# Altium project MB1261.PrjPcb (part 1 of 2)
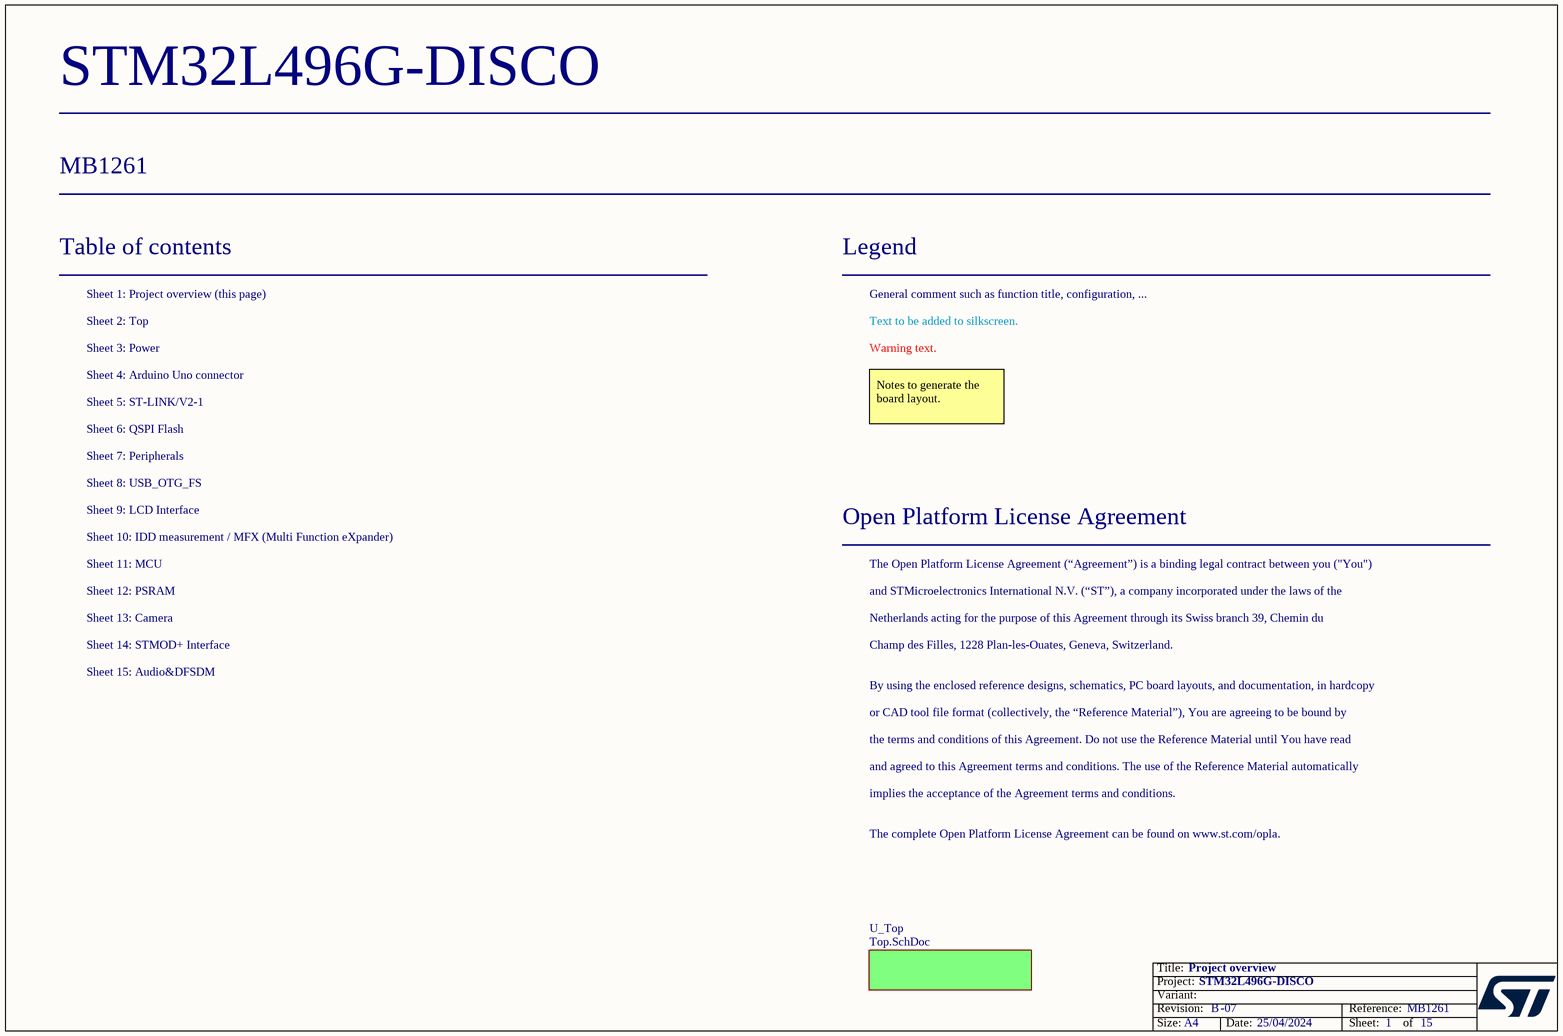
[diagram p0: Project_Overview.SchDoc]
Board_Reference: MB1261; Board_PCB_Revision: B; Board_name: STM32L496G-DISCO; Board_Document_Date: 25/04/2024; Board_Assembly_revision: 07
15 sheets, 337 parts. Net scope: flat (ports and power ports of the same name join across sheets).
Board file: MB1261.PcbDoc
Sheets:
  Project_Overview.SchDoc
    U_Top = Top.SchDoc
      Arduino_ Connectors = Arduino_ Connectors.SchDoc
      Camera Interface = Camera.SchDoc
      IDD = IDD_measurement.SchDoc
      TFT_LCD = LCD.SchDoc
      MCU = MCU.SchDoc
      Peripherals = Peripherals.SchDoc
      Power = Power.SchDoc
      PSRAM = PSRAM.SchDoc
      QSPI = QSPI.SchDoc
      ST_LINK = ST_LINK_V2-1_2.SCHDOC
      OTG = USB_OTG_FS.SchDoc
      STMOD+ = STMOD+.SchDoc
      Audio = Audio.SchDoc

## Sheet Project_Overview.SchDoc: Project overview
size A4; Date: Not used; ApprovedBy: Not used; CheckedBy: Not used; Author: Not used; CompanyName: STMicroelectronics; DrawnBy: Not used; Engineer: Not used; Organization: Not used; Address1: Not used; Address2: Not used; Address3: Not used; Address4: Not used; DocumentNumber: Not used; Revision: Not used; SheetNumber: 1; SheetTotal: 15

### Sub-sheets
U_Top = Top.SchDoc: no entries

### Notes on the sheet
- Table of contents
- Sheet 1: Project overview (this page)
- Legend
- General comment such as function title, configuration, ...
- Sheet 2: Top
- Sheet 3: Power
- Sheet 4: Arduino Uno connector
- Text to be added to silkscreen.
- Warning text.
- Sheet 6: QSPI Flash
- Sheet 5: ST-LINK/V2-1
- Notes to generate the board layout.
- Sheet 7: Peripherals
- Sheet 9: LCD Interface
- Sheet 8: USB_OTG_FS
- Sheet 10: IDD measurement / MFX (Multi Function eXpander)
- Sheet 11: MCU
- Open Platform License Agreement
- The Open Platform License Agreement (“Agreement”) is a binding legal contract between you ("You")
- Sheet 12: PSRAM
- Sheet 13: Camera
- Sheet 14: STMOD+ Interface
- and STMicroelectronics International N.V. (“ST”), a company incorporated under the laws of the
- Netherlands acting for the purpose of this Agreement through its Swiss branch 39, Chemin du
- Champ des Filles, 1228 Plan-les-Ouates, Geneva, Switzerland.
- Sheet 15: Audio&DFSDM
- By using the enclosed reference designs, schematics, PC board layouts, and documentation, in hardcopy
- or CAD tool file format (collectively, the “Reference Material”), You are agreeing to be bound by
- the terms and conditions of this Agreement. Do not use the Reference Material until You have read
- and agreed to this Agreement terms and conditions. The use of the Reference Material automatically
- implies the acceptance of the Agreement terms and conditions.
- The complete Open Platform License Agreement can be found on www.st.com/opla.

## Sheet Top.SchDoc: TOP
size A3; Author: P.A.; CompanyName: STMicroelectronics; Organization: Microcontrollers Division; Address1: 12, Rue Jules HOROWITZ; Address2: 38019 Grenoble; Address3: FRANCE; DocumentNumber: MB1261; Revision: B.01; SheetNumber: 2; SheetTotal: 15; Project: STM32L496G-DISCO
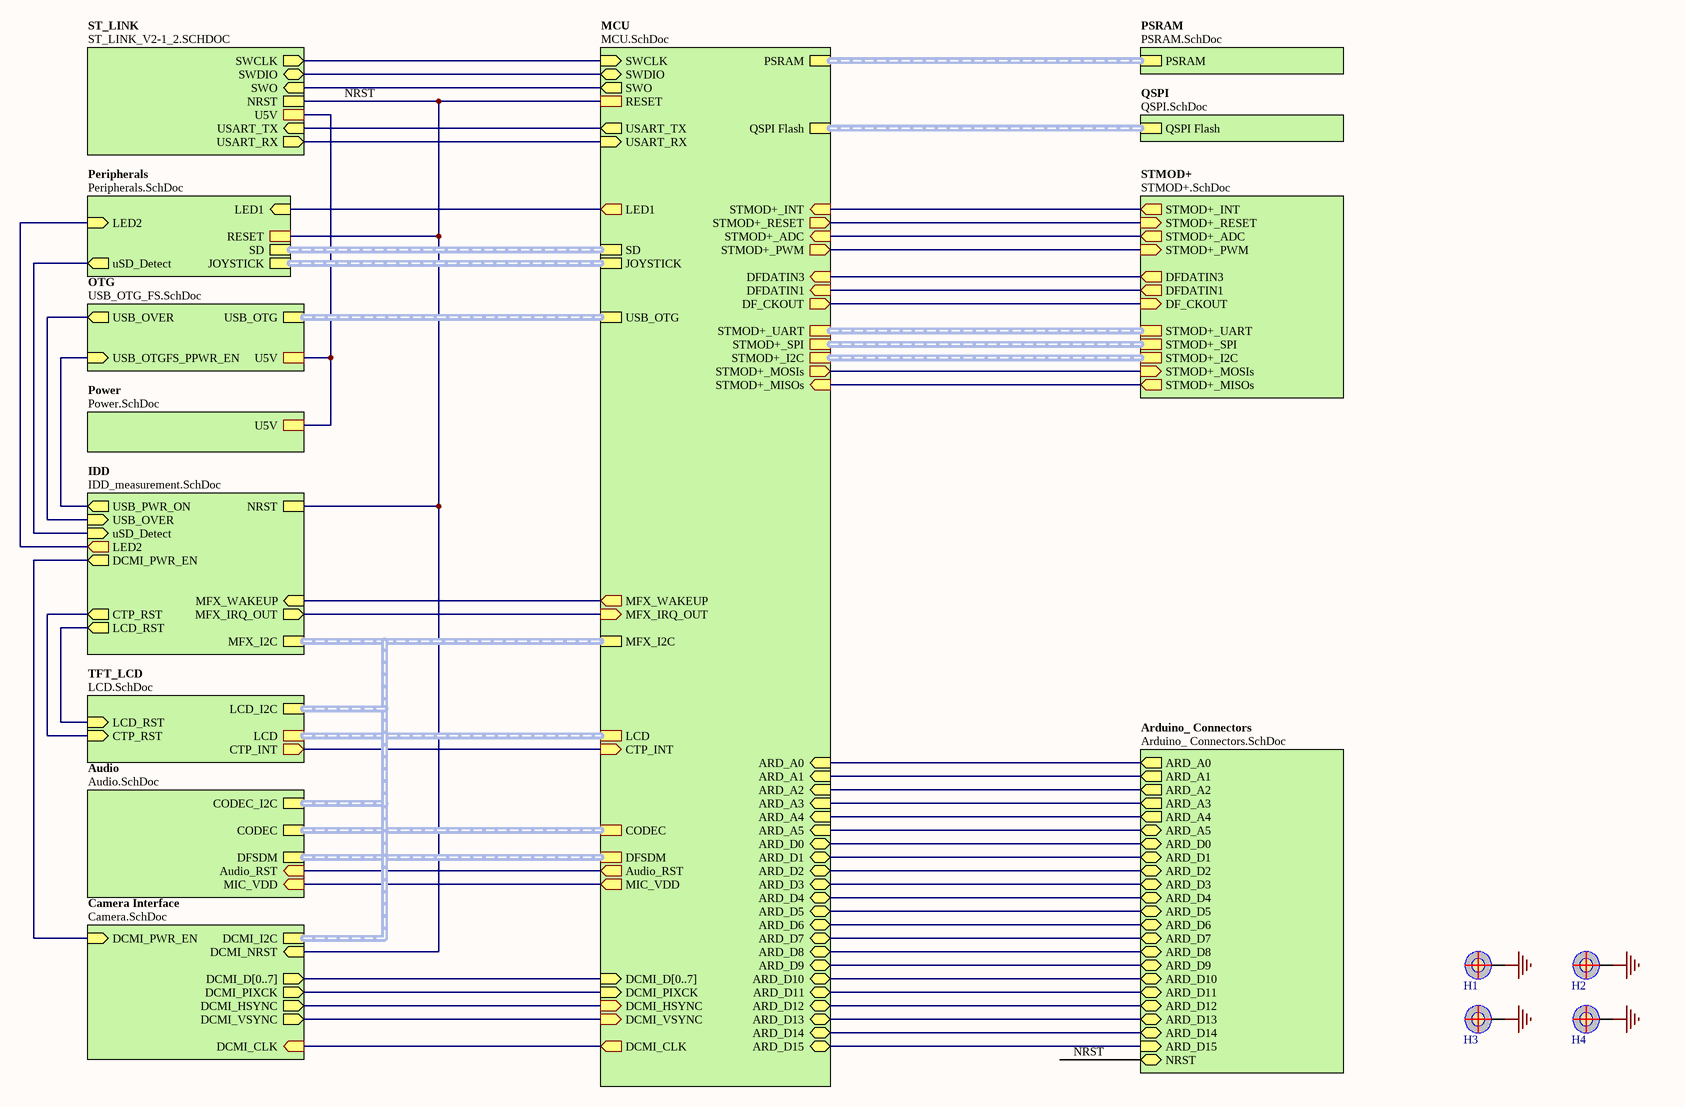
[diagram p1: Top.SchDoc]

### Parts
H1  POSITION HOLE  [Hole_C7d3r5]  (value not drawn)  (no BOM)
H2  POSITION HOLE  [Hole_C7d3r5]  (value not drawn)  (no BOM)
H3  POSITION HOLE  [Hole_C7d3r5]  (value not drawn)  (no BOM)
H4  POSITION HOLE  [Hole_C7d3r5]  (value not drawn)  (no BOM)

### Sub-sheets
Arduino_ Connectors = Arduino_ Connectors.SchDoc: NRST (bidir), ARD_A0 (out), ARD_A1 (out), ARD_A2 (out), ARD_A3 (out), ARD_A4 (out), ARD_A5 (bidir), ARD_D5 (bidir), ARD_D4 (bidir), ARD_D3 (bidir), ARD_D2 (bidir), ARD_D1 (bidir), ARD_D0 (bidir), ARD_D13 (bidir), ARD_D12 (bidir), ARD_D11 (bidir), ARD_D10 (bidir), ARD_D9 (bidir), ARD_D8 (bidir), ARD_D6 (bidir), ARD_D7 (bidir), ARD_D15 (in), ARD_D14 (bidir)
Audio = Audio.SchDoc: CODEC (harness SAI), CODEC_I2C (harness I2C), DFSDM (harness DFSDM), MIC_VDD (in), Audio_RST (in)
Camera Interface = Camera.SchDoc: DCMI_D[0..7] (out), DCMI_NRST (in), DCMI_PWR_EN (in), DCMI_VSYNC (out), DCMI_HSYNC (out), DCMI_PIXCK (out), DCMI_I2C (harness I2C), DCMI_CLK (in)
IDD = IDD_measurement.SchDoc: MFX_IRQ_OUT (out), MFX_WAKEUP (in), NRST, MFX_I2C (harness I2C), USB_PWR_ON (out), DCMI_PWR_EN (out), uSD_Detect (in), USB_OVER (in), CTP_RST (out), LCD_RST (out), LED2 (out)
MCU = MCU.SchDoc: QSPI Flash (harness QSPI), PSRAM (harness PSRAM), SD (harness SD), JOYSTICK (harness JOYSTICK), USB_OTG (harness USB_OTG), MFX_IRQ_OUT (in), MFX_WAKEUP (out), ARD_A0 (in), MFX_I2C (harness I2C), ARD_A1 (in), ARD_A2 (in), ARD_A3 (in), ARD_A4 (in), ARD_A5 (in), ARD_D0 (bidir), ARD_D1 (bidir), ARD_D2 (bidir), ARD_D3 (bidir), ARD_D4 (bidir), ARD_D5 (bidir), ARD_D6 (bidir), ARD_D7 (bidir), ARD_D8 (bidir), ARD_D9 (bidir), ARD_D10 (bidir), ARD_D11 (bidir), ARD_D12 (bidir), ARD_D13 (bidir), ARD_D14 (bidir), ARD_D15 (bidir), USART_TX (out), USART_RX (in), SWCLK (in), SWDIO (bidir), SWO (out), DCMI_D[0..7] (in), DCMI_VSYNC (in), DCMI_HSYNC (in), DCMI_PIXCK (in), STMOD+_UART (harness UART), STMOD+_I2C (harness I2C), STMOD+_INT (in), STMOD+_RESET (out), STMOD+_ADC (in), STMOD+_PWM (out), STMOD+_MOSIs (out), STMOD+_MISOs (in), STMOD+_SPI (harness SPI), DFDATIN3 (in), DFDATIN1 (in), DFSDM (harness DFSDM), MIC_VDD (out), CODEC (harness SAI), LED1 (out), RESET, DCMI_CLK (out), LCD (harness LCD), CTP_INT (in), DF_CKOUT (out), Audio_RST (out)
OTG = USB_OTG_FS.SchDoc: USB_OTG (harness USB_OTG), USB_OTGFS_PPWR_EN (in), USB_OVER (out), U5V
Peripherals = Peripherals.SchDoc: LED1 (in), SD (harness SD), JOYSTICK (harness JOYSTICK), LED2 (in), uSD_Detect (out), RESET
Power = Power.SchDoc: U5V
PSRAM = PSRAM.SchDoc: PSRAM (harness PSRAM)
QSPI = QSPI.SchDoc: QSPI Flash (harness QSPI)
ST_LINK = ST_LINK_V2-1_2.SCHDOC: NRST, SWCLK (out), SWDIO (bidir), SWO (in), USART_TX (in), USART_RX (out), U5V
STMOD+ = STMOD+.SchDoc: STMOD+_INT (out), STMOD+_RESET (in), STMOD+_ADC (out), DFDATIN3 (out), STMOD+_PWM (in), DFDATIN1 (out), STMOD+_UART (harness UART), STMOD+_SPI (harness SPI), STMOD+_I2C (harness I2C), STMOD+_MOSIs (in), STMOD+_MISOs (out), DF_CKOUT (in)
TFT_LCD = LCD.SchDoc: LCD_I2C (harness I2C), CTP_RST (in), LCD_RST (in), LCD (harness LCD), CTP_INT (out)

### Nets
GND: H1.1 H2.1 H3.1 H4.1
NRST: sheet Arduino_ Connectors/NRST, sheet Camera Interface/DCMI_NRST, sheet IDD/NRST, sheet MCU/RESET, sheet Peripherals/RESET, sheet ST_LINK/NRST
(unnamed): sheet Arduino_ Connectors/ARD_A0, sheet MCU/ARD_A0
(unnamed): sheet Arduino_ Connectors/ARD_A1, sheet MCU/ARD_A1  [a separate net that carries the same name]
(unnamed): sheet Arduino_ Connectors/ARD_A2, sheet MCU/ARD_A2  [a separate net that carries the same name]
(unnamed): sheet Arduino_ Connectors/ARD_A3, sheet MCU/ARD_A3  [a separate net that carries the same name]
(unnamed): sheet Arduino_ Connectors/ARD_A4, sheet MCU/ARD_A4  [a separate net that carries the same name]
(unnamed): sheet Arduino_ Connectors/ARD_A5, sheet MCU/ARD_A5  [a separate net that carries the same name]
(unnamed): sheet Arduino_ Connectors/ARD_D5, sheet MCU/ARD_D5  [a separate net that carries the same name]
(unnamed): sheet Arduino_ Connectors/ARD_D4, sheet MCU/ARD_D4  [a separate net that carries the same name]
(unnamed): sheet Arduino_ Connectors/ARD_D3, sheet MCU/ARD_D3  [a separate net that carries the same name]
(unnamed): sheet Arduino_ Connectors/ARD_D2, sheet MCU/ARD_D2  [a separate net that carries the same name]
(unnamed): sheet Arduino_ Connectors/ARD_D1, sheet MCU/ARD_D1  [a separate net that carries the same name]
(unnamed): sheet Arduino_ Connectors/ARD_D0, sheet MCU/ARD_D0  [a separate net that carries the same name]
(unnamed): sheet Arduino_ Connectors/ARD_D13, sheet MCU/ARD_D13  [a separate net that carries the same name]
(unnamed): sheet Arduino_ Connectors/ARD_D12, sheet MCU/ARD_D12  [a separate net that carries the same name]
(unnamed): sheet Arduino_ Connectors/ARD_D11, sheet MCU/ARD_D11  [a separate net that carries the same name]
(unnamed): sheet Arduino_ Connectors/ARD_D10, sheet MCU/ARD_D10  [a separate net that carries the same name]
(unnamed): sheet Arduino_ Connectors/ARD_D9, sheet MCU/ARD_D9  [a separate net that carries the same name]
(unnamed): sheet Arduino_ Connectors/ARD_D8, sheet MCU/ARD_D8  [a separate net that carries the same name]
(unnamed): sheet Arduino_ Connectors/ARD_D6, sheet MCU/ARD_D6  [a separate net that carries the same name]
(unnamed): sheet Arduino_ Connectors/ARD_D7, sheet MCU/ARD_D7  [a separate net that carries the same name]
(unnamed): sheet Arduino_ Connectors/ARD_D15, sheet MCU/ARD_D15  [a separate net that carries the same name]
(unnamed): sheet Arduino_ Connectors/ARD_D14, sheet MCU/ARD_D14  [a separate net that carries the same name]
(unnamed): sheet Camera Interface/DCMI_PWR_EN, sheet IDD/DCMI_PWR_EN  [a separate net that carries the same name]
(unnamed): sheet Camera Interface/DCMI_VSYNC, sheet MCU/DCMI_VSYNC  [a separate net that carries the same name]
(unnamed): sheet Camera Interface/DCMI_HSYNC, sheet MCU/DCMI_HSYNC  [a separate net that carries the same name]
(unnamed): sheet Camera Interface/DCMI_PIXCK, sheet MCU/DCMI_PIXCK  [a separate net that carries the same name]
(unnamed): sheet Camera Interface/DCMI_CLK, sheet MCU/DCMI_CLK  [a separate net that carries the same name]
(unnamed): sheet IDD/MFX_IRQ_OUT, sheet MCU/MFX_IRQ_OUT  [a separate net that carries the same name]
(unnamed): sheet IDD/MFX_WAKEUP, sheet MCU/MFX_WAKEUP  [a separate net that carries the same name]
(unnamed): sheet IDD/USB_PWR_ON, sheet OTG/USB_OTGFS_PPWR_EN  [a separate net that carries the same name]
(unnamed): sheet IDD/uSD_Detect, sheet Peripherals/uSD_Detect  [a separate net that carries the same name]
(unnamed): sheet IDD/USB_OVER, sheet OTG/USB_OVER  [a separate net that carries the same name]
(unnamed): sheet IDD/CTP_RST, sheet TFT_LCD/CTP_RST  [a separate net that carries the same name]
(unnamed): sheet IDD/LCD_RST, sheet TFT_LCD/LCD_RST  [a separate net that carries the same name]
(unnamed): sheet IDD/LED2, sheet Peripherals/LED2  [a separate net that carries the same name]
(unnamed): sheet TFT_LCD/CTP_INT, sheet MCU/CTP_INT  [a separate net that carries the same name]
(unnamed): sheet MCU/USART_TX, sheet ST_LINK/USART_TX  [a separate net that carries the same name]
(unnamed): sheet MCU/USART_RX, sheet ST_LINK/USART_RX  [a separate net that carries the same name]
(unnamed): sheet MCU/SWCLK, sheet ST_LINK/SWCLK  [a separate net that carries the same name]
(unnamed): sheet MCU/SWDIO, sheet ST_LINK/SWDIO  [a separate net that carries the same name]
(unnamed): sheet MCU/SWO, sheet ST_LINK/SWO  [a separate net that carries the same name]
(unnamed): sheet MCU/STMOD+_INT, sheet STMOD+/STMOD+_INT  [a separate net that carries the same name]
(unnamed): sheet MCU/STMOD+_RESET, sheet STMOD+/STMOD+_RESET  [a separate net that carries the same name]
(unnamed): sheet MCU/STMOD+_ADC, sheet STMOD+/STMOD+_ADC  [a separate net that carries the same name]
(unnamed): sheet MCU/STMOD+_PWM, sheet STMOD+/STMOD+_PWM  [a separate net that carries the same name]
(unnamed): sheet MCU/STMOD+_MOSIs, sheet STMOD+/STMOD+_MOSIs  [a separate net that carries the same name]
(unnamed): sheet MCU/STMOD+_MISOs, sheet STMOD+/STMOD+_MISOs  [a separate net that carries the same name]
(unnamed): sheet MCU/DFDATIN3, sheet STMOD+/DFDATIN3  [a separate net that carries the same name]
(unnamed): sheet MCU/DFDATIN1, sheet STMOD+/DFDATIN1  [a separate net that carries the same name]
(unnamed): sheet MCU/MIC_VDD, sheet Audio/MIC_VDD  [a separate net that carries the same name]
(unnamed): sheet MCU/LED1, sheet Peripherals/LED1  [a separate net that carries the same name]
(unnamed): sheet MCU/DF_CKOUT, sheet STMOD+/DF_CKOUT  [a separate net that carries the same name]
(unnamed): sheet MCU/Audio_RST, sheet Audio/Audio_RST  [a separate net that carries the same name]
(unnamed): sheet Power/U5V, sheet ST_LINK/U5V, sheet OTG/U5V  [a separate net that carries the same name]

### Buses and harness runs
bus sheet Camera Interface/DCMI_D[0..7] = sheet MCU/DCMI_D[0..7]
harness sheet Audio/CODEC = sheet MCU/CODEC
harness sheet Audio/CODEC_I2C = sheet Camera Interface/DCMI_I2C = sheet IDD/MFX_I2C = sheet MCU/MFX_I2C = sheet TFT_LCD/LCD_I2C
harness sheet Audio/DFSDM = sheet MCU/DFSDM
harness sheet MCU/JOYSTICK = sheet Peripherals/JOYSTICK
harness sheet MCU/LCD = sheet TFT_LCD/LCD
harness sheet MCU/PSRAM = sheet PSRAM/PSRAM
harness sheet MCU/QSPI Flash = sheet QSPI/QSPI Flash
harness sheet MCU/SD = sheet Peripherals/SD
harness sheet MCU/STMOD+_I2C = sheet STMOD+/STMOD+_I2C
harness sheet MCU/STMOD+_SPI = sheet STMOD+/STMOD+_SPI
harness sheet MCU/STMOD+_UART = sheet STMOD+/STMOD+_UART
harness sheet MCU/USB_OTG = sheet OTG/USB_OTG

## Sheet Arduino_ Connectors.SchDoc: Arduino Uno connector
size A4; Author: P.A.; CompanyName: STMicroelectronics; Organization: Microcontrollers Division; Address1: 12, Rue Jules HOROWITZ; Address2: 38019 Grenoble; Address3: FRANCE; DocumentNumber: MB1261; Revision: B.01; SheetNumber: 4; SheetTotal: 15; Project: STM32L496G-DISCO
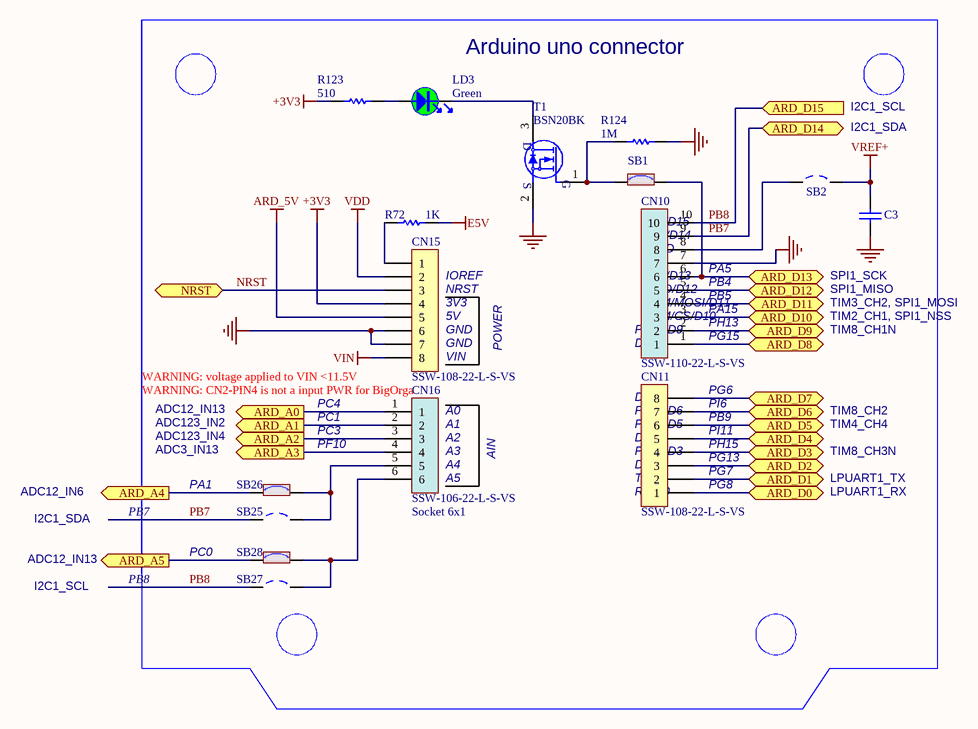
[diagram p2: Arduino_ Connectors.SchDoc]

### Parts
C3  (no value)  [0603C]
CN10  SSW-110-22-L-S-VS  [CON_SAMTEC_SSW-110-22-X-S-VS]
CN11  SSW-108-22-L-S-VS  [SSW-108-22-X-S-VS]
CN15  SSW-108-22-L-S-VS  [SSW-108-22-X-S-VS]
CN16  SSW-106-22-L-S-VS  value Socket 6x1  [CON_SAMTEC_SSW-106-22-X-S-VS]
LD3  value Green  [LED_0603_OSRAM_LG-Q396-PS-35_GREEN_1A2K_H0P4]  (hidden comment: 19-213SY6C/S530-E2/TR8LED)
R72  1K  [0603R]
R123  value 510  [0603R]  (hidden comment: RC0603JR-07510RL)
R124  1M  [0603R]
SB1  Solder Bridge ON  [SB_0603]  (value not drawn)
SB2  Solder Bridge OFF  [SB_0603]  (value not drawn)
SB25  Solder Bridge OFF  [SB_0603]  (value not drawn)
SB26  Solder Bridge ON  [SB_0603]  (value not drawn)
SB27  Solder Bridge OFF  [SB_0603]  (value not drawn)
SB28  Solder Bridge ON  [SB_0603]  (value not drawn)
T1  BSN20BK  [SOT-23]

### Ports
ARD_A0 (out), ARD_A1 (out), ARD_A2 (out), ARD_A3 (out), ARD_A4 (out), ARD_A5 (out), ARD_D0 (bidir), ARD_D1 (bidir), ARD_D2 (bidir), ARD_D3 (bidir), ARD_D4 (bidir), ARD_D5 (bidir), ARD_D6 (bidir), ARD_D7 (bidir), ARD_D8 (bidir), ARD_D9 (bidir), ARD_D10 (bidir), ARD_D11 (bidir), ARD_D12 (bidir), ARD_D13 (bidir), ARD_D14 (bidir), ARD_D15 (in), NRST (bidir)

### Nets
+3V3: CN15.4 R123.1  [project net 3V3_OUT]
ARD_5V: CN15.5
E5V: R72.1
GND: C3.2 CN10.7 CN15.6 CN15.7 R124.2 T1.2(S)
VDD: CN15.2
VIN: CN15.8
VREF+: C3.1 SB2.2
ARD_A0: CN16.1 ; port ARD_A0
ARD_A1: CN16.2 ; port ARD_A1
ARD_A2: CN16.3 ; port ARD_A2
ARD_A3: CN16.4 ; port ARD_A3
ARD_A4: SB26.1 ; port ARD_A4
ARD_A5: SB28.1 ; port ARD_A5
ARD_D0: CN11.1 ; port ARD_D0
ARD_D1: CN11.2 ; port ARD_D1
ARD_D2: CN11.3 ; port ARD_D2
ARD_D3: CN11.4 ; port ARD_D3
ARD_D4: CN11.5 ; port ARD_D4
ARD_D5: CN11.6 ; port ARD_D5
ARD_D6: CN11.7 ; port ARD_D6
ARD_D7: CN11.8 ; port ARD_D7
ARD_D8: CN10.1 ; port ARD_D8
ARD_D9: CN10.2 ; port ARD_D9
ARD_D10: CN10.3 ; port ARD_D10
ARD_D11: CN10.4 ; port ARD_D11
ARD_D12: CN10.5 ; port ARD_D12
ARD_D13: CN10.6 SB1.2 ; port ARD_D13
NRST: CN15.3 ; port NRST
PB7: CN10.9 SB25.1 ; port ARD_D14  [project net ARD_D14]
PB8: CN10.10 SB27.1 ; port ARD_D15  [project net ARD_D15]
NetCN10_8: CN10.8 SB2.1
NetCN15_1: CN15.1 R72.2
NetCN16_5: CN16.5 SB25.2 SB26.2
NetCN16_6: CN16.6 SB27.2 SB28.2
NetLD3_1: LD3.1 R123.2
NetLD3_2: LD3.2 T1.3(D)
NetR124_1: R124.1 SB1.1 T1.1(G)

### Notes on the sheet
- (near LD3) Arduino uno connector
- I2C1_SCL
- I2C1_SDA
- (near CN10) SDA/D14
- SCL/D15
- (near CN10) AVDD
- IOREF
- (near CN15) NRST
- (near CN15) 3V3
- (near CN10) SCK/D13
- (near CN10) MISO/D12
- (near CN10) PWM/MOSI/D11
- (near CN10) GND
- (near CN10) PA15
- (near CN10) PB5
- (near CN10) PB4
- (near CN10) PA5
- TIM3_CH2, SPI1_MOSI
- SPI1_MISO
- (near C3) SPI1_SCK
- WARNING: voltage applied to VIN <11.5V
- (near CN15) 5V
- (near CN15) GND
- (near CN15) VIN
- POWER
- (near CN10) D8
- (near CN10) PWM/D9
- (near CN10) PWM/CS/D10
- (near CN10) PG15
- (near CN10) PH13
- TIM8_CH1N
- TIM2_CH1, SPI1_NSS
- (near CN16) WARNING: CN2-PIN4 is not a input PWR for BigOrga
- ADC3_IN13
- ADC123_IN4
- ADC123_IN2
- ADC12_IN13
- PC4
- PC1
- PC3
- PF10
- (near CN16) A0
- (near CN16) A1
- (near CN16) A2
- (near CN11) D4
- (near CN11) PWM/D5
- (near CN11) PWM/D6
- (near CN11) D7
- (near CN11) PI11
- (near CN11) PB9
- (near CN11) PI6
- PG6
- (near CN11) PH15
- TIM4_CH4
- TIM8_CH2
- ADC12_IN6
- PB7
- PA1
- (near CN16) A3
- (near CN16) A4
- (near CN16) A5
- AIN
- (near CN11) RX/D0
- (near CN11) TX/D1
- (near CN11) D2
- (near CN11) PWM/D3
- (near CN11) PG7
- (near CN11) PG8
- (near CN11) PG13
- LPUART1_TX
- LPUART1_RX
- TIM8_CH3N
- PB8
- PC0

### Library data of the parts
C3 = Cap: Capacitor,100nF,10%,16V,X7R,0603,YAGEO; Manuf_Part_1: CC0603KRX7R7BB104; Ordered by: Subcon
CN10 = MCD-00301: Socket, 10x1, 2.54mm, VR, SMD, T=9.78mm; Part_Type: Connector; Part_Preference: Recommended; Manufacturer: SAMTEC; Component_Country_Of_Origin: China, Costa Rica, Malaysia, USA, Vietnam; ShowFields: YES; ID: 2566
CN11 CN15 = Header 8X1_Female: Header, 8-Pin, Single row,female; Manuf_1: SAMTEC; Ordered by: Subcon; ECCN_US/EU: NA
CN16 = MCD-00299: Socket, 6x1, 2.54mm, VR, SMD, T=9.78mm; Part_Type: Connector; Part_Preference: Recommended; Manufacturer: SAMTEC; Component_Country_Of_Origin: China, Costa Rica, Malaysia, USA, Vietnam; ShowFields: YES; ID: 2569
LD3 = MCD-02901: LED, Green, 2V, 20mA, 0603; Part_Type: Display; Part_Preference: Recommended; Manufacturer: EVERLIGHT; Manufacturer_Part_Number: 19-217/G7C-AN1P2/6T; Partial_Alternate_Internal_Part_Number: MCD-02400; Component_Country_Of_Origin: China; ShowFields: YES; ID: 5017
R72 = res1: Resistor,1K,0603,1%; Manuf_1: YAGEO; Manuf_Part_1: RC0603FR-071KL; Ordered by: Subcon; ECCN_US/EU: NA
R123 = res1: Resistor, 510R , 0603,1%,YAGEO; Ordered by: Subcon; ECCN_US/EU: NA
R124 = res1: Resistor, 1M , 0603; Ordered by: Subcon; ECCN_US/EU: NA
SB1 SB26 SB28 = SB_ON: Manuf_1: YAGEO; Manuf_Part_1: RC0603JR-070RL; Solder: YES; Ordered By: Subcon
SB2 SB25 SB27 = SB_OFF: Solder: NO
T1 = 2N7000: Manuf_1: NXP; Ordered by: Subcon

## Sheet Camera.SchDoc: Camera
size A4; Author: P.A.; CompanyName: STMicroelectronics; Organization: Microcontrollers Division; Address1: 12, Rue Jules HOROWITZ; Address2: 38019 Grenoble; Address3: FRANCE; DocumentNumber: MB1261; Revision: B.01; SheetNumber: 13; SheetTotal: 15; Project: STM32L496G-DISCO
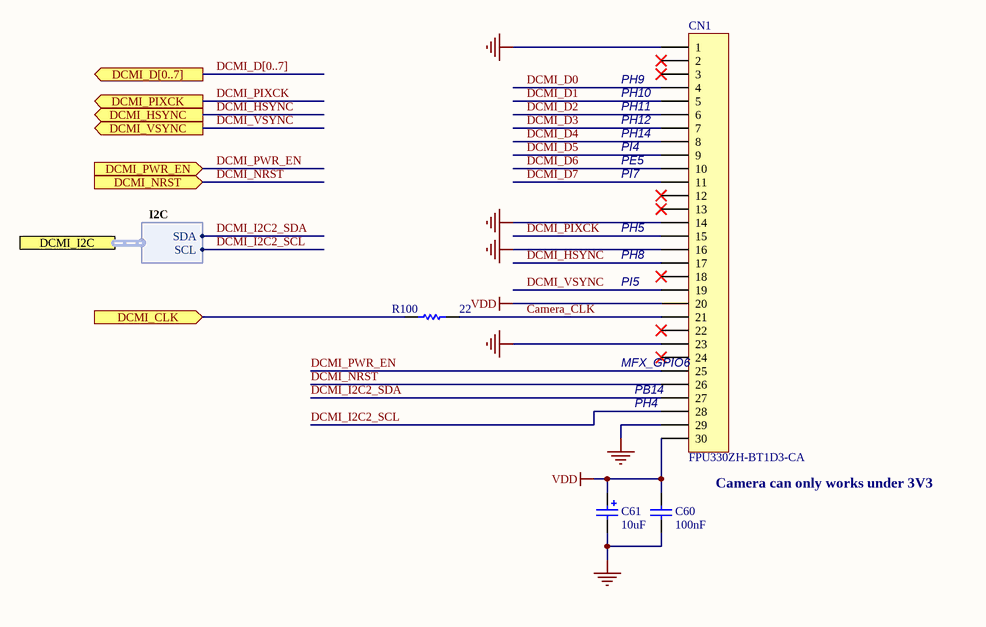
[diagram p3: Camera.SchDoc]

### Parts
C60  value 100nF  [0603C]  (hidden comment: CC0603KRX7R7BB104)
C61  value 10uF  [TAN-A]  (hidden comment: TAJA106K016R)
CN1  FPU330ZH-BT1D3-CA  [FPU330ZH-BT1D3-CA]
R100  value 22  [0603R]  (hidden comment: RC0603JR-0722RL)

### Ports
DCMI_CLK (in), DCMI_D[0..7] (out), DCMI_HSYNC (out), DCMI_I2C (harness I2C), DCMI_NRST (in), DCMI_PIXCK (out), DCMI_PWR_EN (in), DCMI_VSYNC (out)

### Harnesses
I2C: SDA, SCL

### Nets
GND: C60.2 C61.2 CN1.1 CN1.14 CN1.16 CN1.23 CN1.29
VDD: C60.1 C61.1 CN1.20 CN1.30
Camera_CLK: CN1.21 R100.1
DCMI_CLK: R100.2 ; port DCMI_CLK
DCMI_D0: CN1.4
DCMI_D1: CN1.5
DCMI_D2: CN1.6
DCMI_D3: CN1.7
DCMI_D4: CN1.8
DCMI_D5: CN1.9
DCMI_D6: CN1.10
DCMI_D7: CN1.11
DCMI_HSYNC: CN1.17 ; port DCMI_HSYNC
DCMI_I2C2_SCL: CN1.28 ; port DCMI_I2C.SCL
DCMI_I2C2_SDA: CN1.27 ; port DCMI_I2C.SDA
DCMI_NRST: CN1.26 ; port DCMI_NRST
DCMI_PIXCK: CN1.15 ; port DCMI_PIXCK
DCMI_PWR_EN: CN1.25 ; port DCMI_PWR_EN
DCMI_VSYNC: CN1.19 ; port DCMI_VSYNC

Not connected (* = marked no-connect by the designer): CN1 2* 3* 12* 13* 18* 22* 24*

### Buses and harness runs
bus DCMI_D[0..7] = port DCMI_D[0..7]

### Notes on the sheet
- (near CN1) PH10
- (near CN1) PH11
- (near CN1) PH9
- (near CN1) PE5
- (near CN1) PH12
- (near CN1) PH14
- (near CN1) PI4
- (near CN1) PI7
- (near CN1) PH5
- (near CN1) PH8
- (near CN1) PI5
- (near CN1) MFX_GPIO6
- (near CN1) PH4
- (near CN1) PB14
- Camera can only works under 3V3

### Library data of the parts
C60 = Cap: Capacitor,100nF,10%,16V,X7R,0603,YAGEO; Ordered by: Subcon
C61 = Cap Pol1: TAN Capacitor,10uF,10%,16V,A Type,AVX; Ordered by: Subcon; ECCN_US/EU: NA
CN1 = FPU330ZH-BT1D3-CA: TOWNES -  Connector FFC/FPC ZIF 0.5mm 30 pins, Lower Contacts; Manuf_Part_2: TFP-A330ZH-BT1-ECX; Ordered by: Subcon
R100 = res1: Resistor, 22 ,0603,1%,YAGEO; Ordered by: Subcon; ECCN_US/EU: NA

## Sheet IDD_measurement.SchDoc: IDD measurement / MFX (Multi Function eXpander)
size A3; Date: 3/31/2015; Author: P.A.; CompanyName: STMicroelectronics; Organization: Microcontrollers Division; Address1: 12, Rue Jules HOROWITZ; Address2: 38019 Grenoble; Address3: FRANCE; DocumentNumber: MB1261; Revision: B.01; SheetNumber: 10; SheetTotal: 15; Project: STM32L496G-DISCO
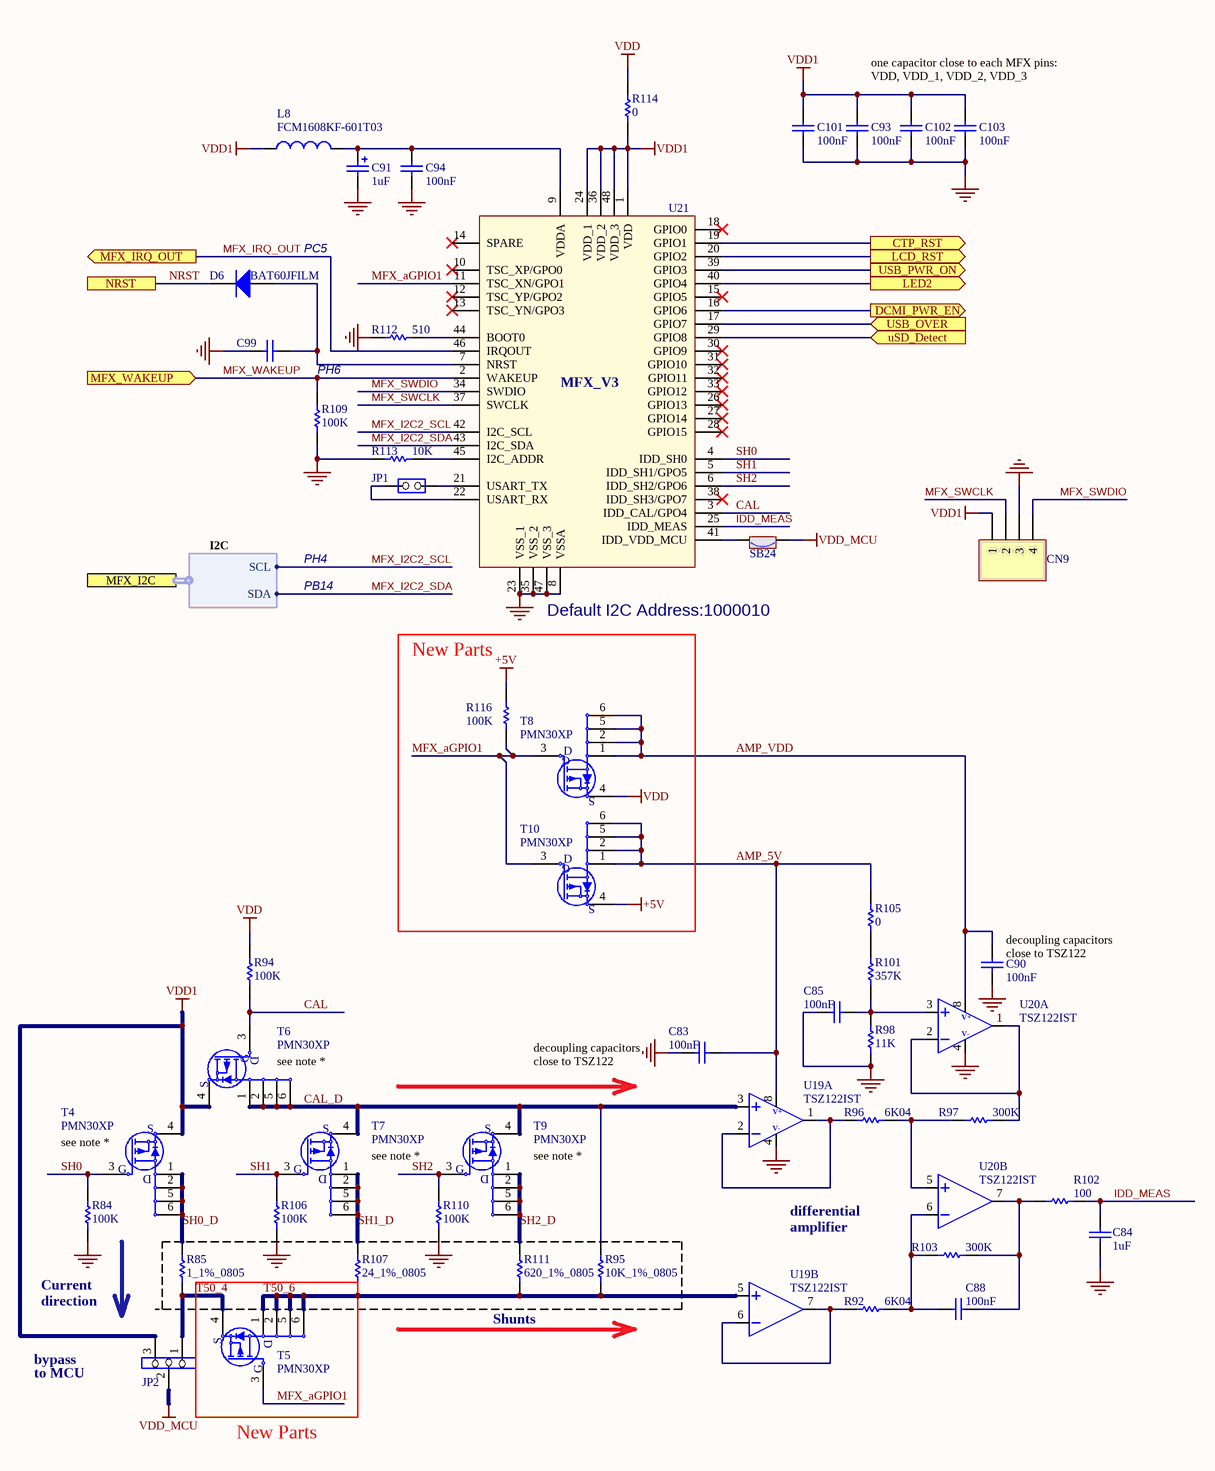
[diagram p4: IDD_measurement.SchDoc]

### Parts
C83  value 100nF  [0603C]  (hidden comment: CC0603KRX7R7BB104)
C84  value 1uF  [0603C]  (hidden comment: CC0603KRX5R7BB105)
C85  value 100nF  [0603C]  (hidden comment: CC0603KRX7R7BB104)
C88  value 100nF  [0603C]  (hidden comment: CC0603KRX7R7BB104)
C90  value 100nF  [0603C]  (hidden comment: CC0603KRX7R7BB104)
C91  value 1uF  [TAN-A]  (hidden comment: TAJA105K016R)
C93  value 100nF  [0603C]  (hidden comment: CC0603KRX7R7BB104)
C94  value 100nF  [0603C]  (hidden comment: CC0603KRX7R7BB104)
C99  (no value)  [0603C]
C101  value 100nF  [0603C]  (hidden comment: CC0603KRX7R7BB104)
C102  value 100nF  [0603C]  (hidden comment: CC0603KRX7R7BB104)
C103  value 100nF  [0603C]  (hidden comment: CC0603KRX7R7BB104)
CN9  (no value)  [HDR_1X4_2R54]
D6  BAT60JFILM  [SOD-323]
JP1  (no value)  [SIP2]
JP2  3 PIN Jumper  [SIP3]  (value not drawn)
L8  FCM1608KF-601T03  [L0603]
R84  value 100K  [0603R]  (hidden comment: RC0603FR-07100KL)
R85  1_1%_0805  [0805R]
R92  value 6K04  [0603R]  (hidden comment: RC0603FR-076K04L)
R94  value 100K  [0603R]  (hidden comment: RC0603FR-07100KL)
R95  10K_1%_0805  [0805R]
R96  value 6K04  [0603R]  (hidden comment: RC0603FR-076K04L)
R97  value 300K  [0603R]  (hidden comment: RC0603FR-07300KL)
R98  value 11K  [0603R]  (hidden comment: RC0603FR-0711KL)
R101  value 357K  [0603R]  (hidden comment: RC0603FR-07357KL)
R102  value 100  [0603R]  (hidden comment: RC0603JR-07100RL)
R103  value 300K  [0603R]  (hidden comment: RC0603FR-07300KL)
R105  value 0  [0603R]  (hidden comment: RC0603JR-070RL)
R106  value 100K  [0603R]  (hidden comment: RC0603FR-07100KL)
R107  24_1%_0805  [0805R]
R109  value 100K  [0603R]  (hidden comment: RC0603FR-07100KL)
R110  value 100K  [0603R]  (hidden comment: RC0603FR-07100KL)
R111  620_1%_0805  [0805R]
R112  value 510  [0603R]  (hidden comment: RC0603FR-07510RL)
R113  value 10K  [0603R]  (hidden comment: RC0603FR-0710KL)
R114  value 0  [0603R]  (hidden comment: RC0603JR-070RL)
R116  value 100K  [0603R]  (hidden comment: RC0603FR-07100KL)
SB24  Solder Bridge ON  [SB_0603]  (value not drawn)
T4  PMN30XP  [MOS_SOT23-6L]
T5  PMN30XP  [MOS_SOT23-6L]
T6  PMN30XP  [MOS_SOT23-6L]
T7  PMN30XP  [MOS_SOT23-6L]
T8  PMN30XP  [MOS_SOT23-6L]
T9  PMN30XP  [MOS_SOT23-6L]
T10  PMN30XP  [MOS_SOT23-6L]
U19  TSZ122IST  [miniSO8]  (parts A,B of 2)
U20  TSZ122IST  [miniSO8]  (parts A,B of 2)
U21  STM32L152CCT6  [LQFP48_0R5_9X9]  (value not drawn)

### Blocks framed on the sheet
New Parts: R116 T8 T10

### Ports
CTP_RST (out), DCMI_PWR_EN (out), LCD_RST (out), LED2 (out), MFX_I2C (harness I2C), MFX_IRQ_OUT (out), MFX_WAKEUP (in), NRST, USB_OVER (in), USB_PWR_ON (out), uSD_Detect (in)

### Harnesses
I2C: SDA, SCL

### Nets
+5V: R116.2 T10.4(S)
GND: C83.1 C84.2 C85.1 C90.2 C91.2 C93.2 C94.2 C99.1 C101.2 C102.2 C103.2 CN9.3 R84.1 R98.2 R106.1 R109.1 R110.1 R112.2 R113.2 U19.4 U20.4 U21.8(VSSA) U21.23(VSS_1) U21.35(VSS_2) U21.47(VSS_3)
VDD: R94.2 R114.1 T8.4(S)
VDD1: C93.1 C101.1 C102.1 C103.1 CN9.1 JP2.3 L8.1 R114.2 T4.4(S) T6.4(S) U21.1(VDD) U21.24(VDD_1) U21.36(VDD_2) U21.48(VDD_3)
VDD_MCU: JP2.2 SB24.1
AMP_5V: C83.2 R105.2 T10.1(S) T10.2(S) T10.5(D) T10.6(D) U19.8
AMP_VDD: C90.1 T8.1(S) T8.2(S) T8.5(D) T8.6(D) U20.8
CAL: R94.1 T6.3(G) U21.3(IDD_CAL/GPO4)
CAL_D: R95.2 T6.1(S) T6.2(S) T6.5(D) T6.6(D) T7.4(S) T9.4(S) U19.3
DCMI_PWR_EN: U21.16(GPIO6) ; port DCMI_PWR_EN
IDD_MEAS: C84.1 R102.1 U21.25(IDD_MEAS)
LCD_RST: U21.20(GPIO2) ; port LCD_RST
MFX_aGPIO1: R116.1 T5.3(G) T8.3(G) T10.3(G) U21.11(TSC_XN/GPO1)
MFX_I2C2_SCL: U21.42(I2C_SCL) ; port MFX_I2C.SCL  [project net I2C2_SCL]
MFX_I2C2_SDA: U21.43(I2C_SDA) ; port MFX_I2C.SDA  [project net I2C2_SDA]
MFX_IRQ_OUT: U21.46(IRQOUT) ; port MFX_IRQ_OUT
MFX_SWCLK: CN9.2 U21.37(SWCLK)
MFX_SWDIO: CN9.4 U21.34(SWDIO)
MFX_WAKEUP: R109.2 U21.2(WAKEUP) ; port MFX_WAKEUP
NRST: D6.2(K) ; port NRST
SH0: R84.2 T4.3(G) U21.4(IDD_SH0)
SH0_D: R85.2 T4.1(S) T4.2(S) T4.5(D) T4.6(D)
SH1: R106.2 T7.3(G) U21.5(IDD_SH1/GPO5)
SH1_D: R107.2 T7.1(S) T7.2(S) T7.5(D) T7.6(D)
SH2: R110.2 T9.3(G) U21.6(IDD_SH2/GPO6)
SH2_D: R111.2 T9.1(S) T9.2(S) T9.5(D) T9.6(D)
T50_4: JP2.1 R85.1 T5.4(S)
T50_6: R95.1 R107.1 R111.1 T5.1(S) T5.2(S) T5.5(D) T5.6(D) U19.5
USB_OTGFS_OVRCR: U21.17(GPIO7) ; port USB_OVER
uSD_Detect: U21.29(GPIO8) ; port uSD_Detect
NetC85_2: C85.2 R98.1 R101.2 U20.3
NetC88_1: C88.1 R92.1 R103.1 U20.6
NetC88_2: C88.2 R102.2 R103.2 U20.7
NetC91_1: C91.1 C94.1 L8.2 U21.9(VDDA)
NetC99_2: C99.2 D6.1(A) U21.7(NRST)
NetCN13_7: U21.19(GPIO1) ; port CTP_RST
NetJP1_1: JP1.1(COMMON) U21.22(USART_RX)
NetJP1_2: JP1.2(NO) U21.21(USART_TX)
NetR1_1: U21.40(GPIO4) ; port LED2
NetR92_2: R92.2 U19.6 U19.7
NetR96_1: R96.1 R97.1 U20.5
NetR96_2: R96.2 U19.1 U19.2
NetR97_2: R97.2 U20.1 U20.2
NetR101_1: R101.1 R105.1
NetR112_1: R112.1 U21.44(BOOT0)
NetR113_1: R113.1 U21.45(I2C_ADDR)
NetSB24_2: SB24.2 U21.41(IDD_VDD_MCU)
NetU21_39: U21.39(GPIO3) ; port USB_PWR_ON

Not connected (* = marked no-connect by the designer): U21 10(TSC_XP/GPO0)* 12(TSC_YP/GPO2)* 13(TSC_YN/GPO3)* 14(SPARE)* 15(GPIO5)* 18(GPIO0)* 26(GPIO13)* 27(GPIO14)* 28(GPIO15)* 30(GPIO9)* 31(GPIO10)* 32(GPIO11)* 33(GPIO12)* 38(IDD_SH3/GPO7)*

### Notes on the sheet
- one capacitor close to each MFX pins: VDD, VDD_1, VDD_2, VDD_3
- PC5
- PH6
- PB14
- PH4
- (near U21) Default I2C Address:1000010
- (near C90) decoupling capacitors
  close to TSZ122
- (near T6) see note *
- (near C83) decoupling capacitors
  close to TSZ122
- (near T4) see note *
- see note *
- (near T9) see note *
- differential
  amplifier
- Current direction
- Shunts
- to MCU
- bypass
- New Parts

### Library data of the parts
C83 C85 C88 C90 C93 C94 C101-C103 = Cap: as C60 on sheet Camera
C84 = Cap: Capacitor,1uF,0603,16V,10%,X5R,YAGEO; Ordered by: Subcon
C91 = Cap Pol1: Tan Capacitor,1uF,10%,16V,Tan-A,TAJA105K016R; Manuf_1: AVX; Ordered by: Subcon; ECCN_US/EU: NA
C99 = Cap: as C3 on sheet Arduino_ Connectors
CN9 = Header 4: Header, 4-Pin; ECCN_US/EU: [N/A]; Ordered by: Subcon
D6 = BAT60JFILM: Provided: STM; ECCN_US/EU: EAR99/NEC; Ref St: 9151097
JP1 = JP2: 2 PIN Jumper; Manuf_1: lyconn; Manuf_Part_1: 313102S111116; Ordered by: Subcon; Assembly: with jumper; ECCN_US/EU: [N/A]
JP2 = Jumper3: Jumper 3 pins; Manuf_1: lyconn; Manuf_Part_1: 313103S111116; Ordered by: Subcon
L8 = MCD-00047: Ferrite bead, 600R @1 00MHz, +/-25%, 350mA, 0R5, 0603, T=0.8mm; Part_Type: Inductor; Part_Preference: Recommended; Manufacturer: TAI-TECH; Partial_Alternate_Internal_Part_Number: MCD-02959; Component_Country_Of_Origin: Unknown; ShowFields: YES; ID: 2546
R84 R94 R106 R109 R110 R116 = res1: Resistor,100K,0603,1%,YAGEO; Ordered by: Subcon; ECCN_US/EU: NA
R85 = Res_1_1%_0805: Resistor,1,0805,1%,YAGEO; Manuf_Part_1: RC0805FR-071RL; Value: 1; Ordered by: Subcon
R92 R96 = res1: Resistor,6.04K,0603,1%,YAGEO; Ordered by: Subcon; ECCN_US/EU: NA
R95 = Res_10K_1%_0805: Resistor,10K,0805,1%,YAGEO; Manuf_Part_1: RC0805FR-0710KL; Ordered by: Subcon
R97 R103 = res1: Resistor,300K,0603,1%,YAGEO; Ordered by: Subcon; ECCN_US/EU: NA
R98 = res1: Resistor,11K,0603,1%,YAGEO; Ordered by: Subcon; ECCN_US/EU: NA
R101 = res1: Resistor,357K,0603,1%,YAGEO; Ordered by: Subcon; ECCN_US/EU: NA
R102 = res1: Resistor, 100 ,0603,1%,YAGEO; Ordered by: Subcon; ECCN_US/EU: NA
R105 R114 = res1: Resistor, 0 ,0603,1%,YAGEO; Ordered by: Subcon; ECCN_US/EU: NA
R107 = Res_24_1%_0805: Resistor,24,0805,1%,YAGEO; Manuf_Part_1: RC0805FR-0724RL; Value: 24; Ordered by: Subcon
R111 = Res_620_1%_0805: Resistor,620,0805,1%,YAGEO; Manuf_Part_1: RC0805FR-07620RL; Value: 620; Ordered by: Subcon
R112 = res1: Resistor,510R,0603,1%,YAGEO; Ordered by: Subcon; ECCN_US/EU: NA
R113 = res1: Resistor,10K,0603,1%,YAGEO; Ordered by: Subcon; ECCN_US/EU: NA
SB24 = SB_ON: as SB1 on sheet Arduino_ Connectors
T4-T10 = MCD-01926: 20 V, P-channel Trench MOSFET; Part_Type: IC; Part_Preference: Recommended; Manufacturer: NEXPERIA; Order_Code_RS: 153-0671
U19 U20 = TSZ122IST: Very high accuracy (5 礦) zero drift 5 V dual OpAmp; Manuf_1: STM; ECCN_US/EU: EAR99/NEC; Provided: ST; Ref St: xxxxxxxxx
U21 = MFX: Multifunction expander; Manuf_1: STM

## Sheet LCD.SchDoc: LCD Interface
size A3; Author: P.A.; CompanyName: STMicroelectronics; Organization: Microcontrollers Division; Address1: 12, Rue Jules HOROWITZ; Address2: 38019 Grenoble; Address3: FRANCE; DocumentNumber: MB1261; Revision: B.01; SheetNumber: 9; SheetTotal: 15; Project: STM32L496G-DISCO
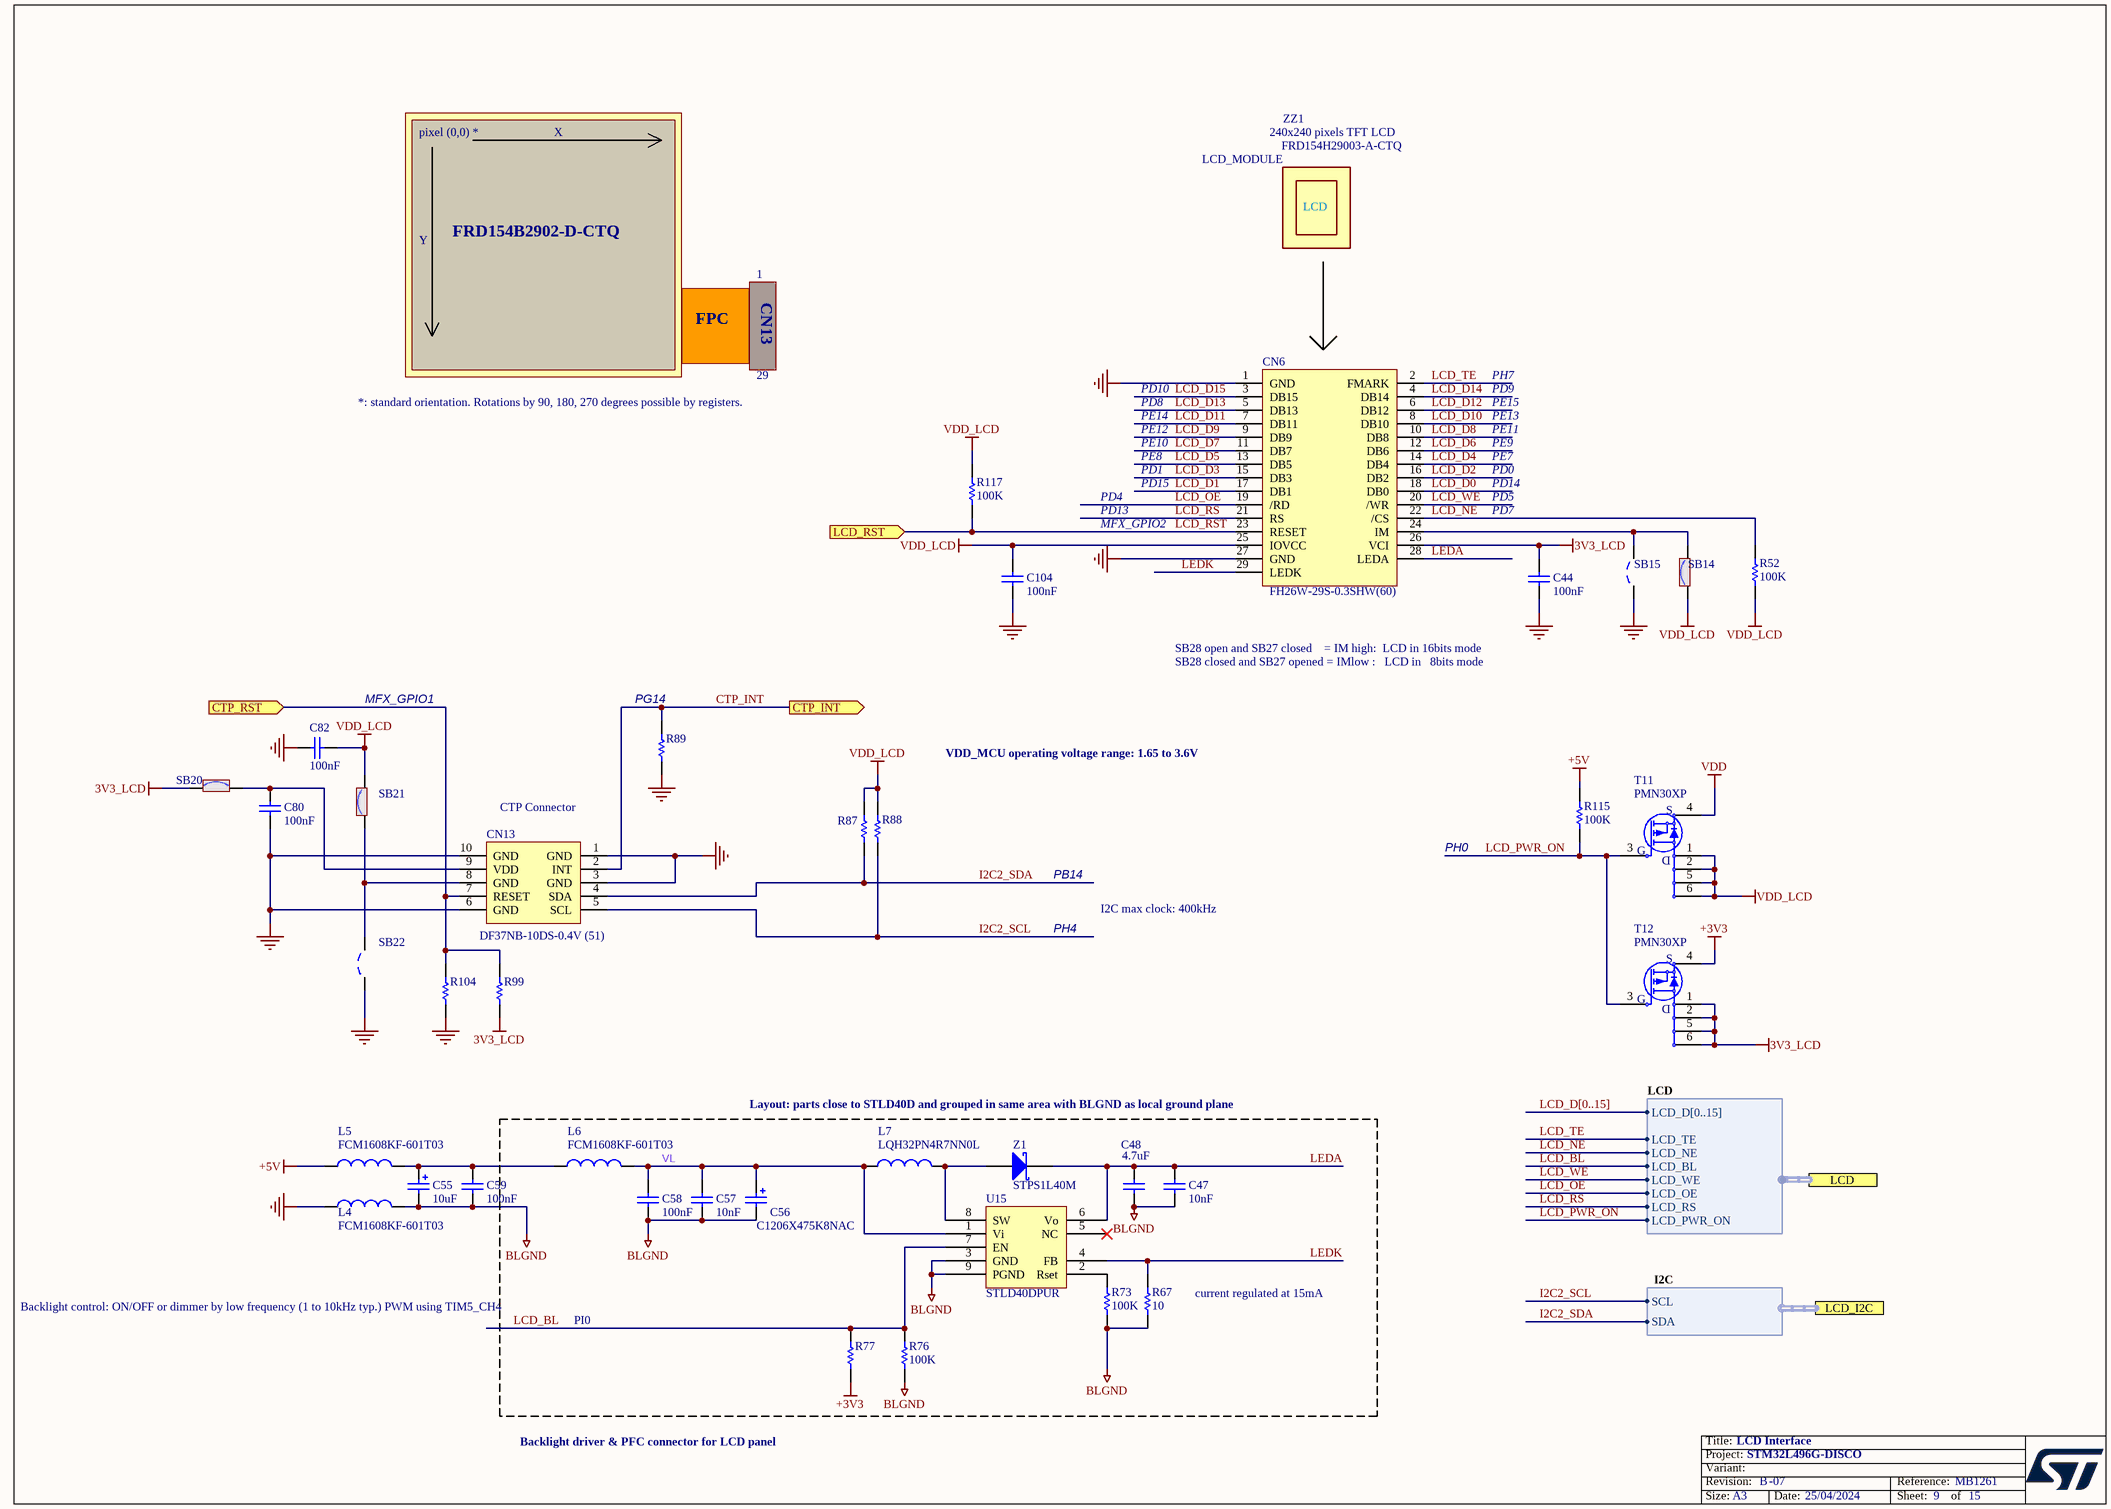
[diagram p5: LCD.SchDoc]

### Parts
C44  value 100nF  [0603C]  (hidden comment: CC0603KRX7R7BB104)
C47  value 10nF  [C0603]  (hidden comment: CC0603KRX7R9BB103)
C48  value 4.7uF  [1206C]  (hidden comment: CC1206KKX7R9BB475)
C55  value 10uF  [TAN-A]  (hidden comment: TAJA106K016R)
C56  C1206X475K8NAC  [1206C]
C57  value 10nF  [C0603]  (hidden comment: CC0603KRX7R9BB103)
C58  value 100nF  [0603C]  (hidden comment: CC0603KRX7R7BB104)
C59  value 100nF  [0603C]  (hidden comment: CC0603KRX7R7BB104)
C80  value 100nF  [0603C]  (hidden comment: CC0603KRX7R7BB104)
C82  value 100nF  [0603C]  (hidden comment: CC0603KRX7R7BB104)
C104  value 100nF  [0603C]  (hidden comment: CC0603KRX7R7BB104)
CN6  FH26W-29S-0.3SHW(60)  [FH26-29S-0R3SHW]
CN13  DF37NB-10DS-0.4V (51)  [DF37NB-10DS-0R4V]
L4  FCM1608KF-601T03  [L0603]
L5  FCM1608KF-601T03  [L0603]
L6  FCM1608KF-601T03  [L0603]
L7  LQH32PN4R7NN0L  [1210L]
R52  value 100K  [0603R]  (hidden comment: RC0603FR-07100KL)
R67  value 10  [0603R]  (hidden comment: RC0603FR-0710RL)
R73  value 100K  [0603R]  (hidden comment: RC0603FR-07100KL)
R76  value 100K  [0603R]  (hidden comment: RC0603FR-07100KL)
R77  (no value)  [0603R]
R87  (no value)  [0603R]
R88  (no value)  [0603R]
R89  (no value)  [0603R]
R99  (no value)  [0603R]
R104  (no value)  [0603R]
R115  value 100K  [0603R]  (hidden comment: RC0603FR-07100KL)
R117  value 100K  [0603R]  (hidden comment: RC0603FR-07100KL)
SB14  Solder Bridge ON  [SB_0603]  (value not drawn)
SB15  Solder Bridge OFF  [SB_0603]  (value not drawn)
SB20  Solder Bridge ON  [SB_0603]  (value not drawn)
SB21  Solder Bridge ON  [SB_0603]  (value not drawn)
SB22  Solder Bridge OFF  [SB_0603]  (value not drawn)
T11  PMN30XP  [MOS_SOT23-6L]
T12  PMN30XP  [MOS_SOT23-6L]
U15  STLD40DPUR  [SON8_0R65_3X3]
Z1  STPS1L40M  [DO-216AA]
ZZ1  LCD_MODULE  value FRD154H29003-A-CTQ  (mechanical)

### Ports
CTP_INT (out), CTP_RST (in), LCD (harness LCD), LCD_I2C (harness I2C), LCD_RST (in)

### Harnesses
LCD: LCD_NE, LCD_BL, LCD_WE, LCD_OE, LCD_D[0..15], LCD_RS, LCD_PWR_ON, LCD_TE
I2C: SDA, SCL

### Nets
3V3_LCD: C44.1 CN6.26(VCI) R99.2 SB20.1 T12.1(S) T12.2(S) T12.5(D) T12.6(D)
+3V3: R77.2 T12.4(S)  [project net 3V3_OUT]
+5V: L5.1 R115.1
BLGND: C47.2 C48.2 C55.2 C56.2 C57.2 C58.2 C59.2 L4.2 R67.2 R73.2 R76.2 U15.3(GND) U15.9(PGND)
GND: C44.2 C80.2 C82.2 C104.2 CN6.1(GND) CN6.27(GND) CN13.1(GND) CN13.3(GND) CN13.6(GND) CN13.10(GND) L4.1 R89.2 R104.2 SB15.1 SB22.1
VDD: T11.4(S)
VDD_LCD: C82.1 C104.1 CN6.25(IOVCC) R52.2 R87.2 R88.1 R117.1 SB14.1 SB21.2 T11.1(S) T11.2(S) T11.5(D) T11.6(D)
CTP_INT: CN13.2(INT) R89.1 ; port CTP_INT
I2C2_SCL: CN13.5(SCL) R88.2 ; port LCD_I2C.SCL
I2C2_SDA: CN13.4(SDA) R87.1 ; port LCD_I2C.SDA
LCD_BL: R76.1 R77.1 U15.7(EN) ; port LCD.LCD_BL
LCD_D0: CN6.18(DB0)  [project net D0]
LCD_D1: CN6.17(DB1)  [project net D1]
LCD_D2: CN6.16(DB2)  [project net D2]
LCD_D3: CN6.15(DB3)  [project net D3]
LCD_D4: CN6.14(DB4)  [project net D4]
LCD_D5: CN6.13(DB5)  [project net D5]
LCD_D6: CN6.12(DB6)  [project net D6]
LCD_D7: CN6.11(DB7)  [project net D7]
LCD_D8: CN6.10(DB8)  [project net D8]
LCD_D9: CN6.9(DB9)  [project net D9]
LCD_D10: CN6.8(DB10)  [project net D10]
LCD_D11: CN6.7(DB11)  [project net D11]
LCD_D12: CN6.6(DB12)  [project net D12]
LCD_D13: CN6.5(DB13)  [project net D13]
LCD_D14: CN6.4(DB14)  [project net D14]
LCD_D15: CN6.3(DB15)  [project net D15]
LCD_NE: CN6.22(/CS) R52.1 ; port LCD.LCD_NE
LCD_OE: CN6.19(/RD) ; port LCD.LCD_OE
LCD_PWR_ON: R115.2 T11.3(G) T12.3(G) ; port LCD.LCD_PWR_ON
LCD_RS: CN6.21(RS) ; port LCD.LCD_RS
LCD_RST: CN6.23(RESET) R117.2 ; port LCD_RST
LCD_TE: CN6.2(FMARK) ; port LCD.LCD_TE
LCD_WE: CN6.20(/WR) ; port LCD.LCD_WE
LEDA: C47.1 C48.1 CN6.28(LEDA) U15.6(Vo) Z1.2(K)
LEDK: CN6.29(LEDK) R67.1 U15.4(FB)
VL: C56.1 C57.1 C58.1 L6.2 L7.1 U15.1(Vi)
NetC55_1: C55.1 C59.1 L5.2 L6.1
NetC80_1: C80.1 CN13.9(VDD) SB20.2
NetCN6_24: CN6.24(IM) SB14.2 SB15.2
NetCN13_7: CN13.7(RESET) R99.1 R104.1 ; port CTP_RST
NetCN13_8: CN13.8(GND) SB21.1 SB22.2
NetL7_2: L7.2 U15.8(SW) Z1.1(A)
NetR73_1: R73.1 U15.2(Rset)

Not connected (* = marked no-connect by the designer): U15 5(NC)*

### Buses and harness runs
bus LCD_D[0..15]

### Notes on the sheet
- pixel (0,0) *
- X
- (near ZZ1) 240x240 pixels TFT LCD
- Y
- FRD154B2902-D-CTQ
- 1
- CN13
- FPC
- 29
- PH7
- *: standard orientation. Rotations by 90, 180, 270 degrees possible by registers.
- PE10
- PE12
- PE14
- PD8
- PD10
- PE9
- PE11
- PE13
- PE15
- PD9
- PD4
- PD13
- PD15
- PD1
- PE8
- PD7
- PD5
- PD14
- PD0
- PE7
- MFX_GPIO2
- MFX_GPIO1
- (near R89) PG14
- SB28 open and SB27 closed    = IM high:  LCD in 16bits mode
  SB28 closed and SB27 opened = IMlow :   LCD in   8bits mode
- VDD_MCU operating voltage range: 1.65 to 3.6V
- (near CN13) CTP Connector
- PH0
- PB14
- I2C max clock: 400kHz
- PH4
- Layout: parts close to STLD40D and grouped in same area with BLGND as local ground plane
- Backlight control: ON/OFF or dimmer by low frequency (1 to 10kHz typ.) PWM using TIM5_CH4
- PI0
- (near R67) current regulated at 15mA
- Backlight driver & PFC connector for LCD panel

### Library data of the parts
C44 C58 C59 C80 C82 C104 = Cap: as C60 on sheet Camera
C47 C57 = MCD-00017: Capacitor, MLCC, 10nF, 50V, X7R, +/-10%, 0603, T=0.8mm; Part_Preference: Recommended; Manufacturer: YAGEO; Order_Code_RS: 722236; Component_Country_Of_Origin: China; ShowFields: YES; ID: 2500
C48 = CAP: Capacitor,4.7uF,50V,X7R,10%,1206; Manuf_1: YAGEO; Ordered by: Subcon; ECCN_US/EU: NA
C55 = Cap Pol1: as C61 on sheet Camera
C56 = Cap Pol1: Capacitor,4.7uF,±10%,X7R,10V,1206,C1206X475K8NAC; Manuf_1: Kemet; Ordered by: Subcon; ECCN_US/EU: NA
CN6 = FH26-29S-0.3SHW: 29pins FPC connector; Manuf_1: Hirose; Ordered by: Subcon; ECCN_US/EU: NA
CN13 = Header 5X2A: Header, 5-Pin, Dual row; Manuf_1: Hirose; Ordered by: Subcon; ECCN_US/EU: NA
L4-L6 = MCD-00047: as L8 on sheet IDD_measurement
L7 = Inductor: IND,4.7uH,1A,1210,LQH32PN4R7NN0L; Manuf_1: Murata; Value: 100uH; Ordered by: Subcon; ECCN_US/EU: NA
R52 R73 R76 R115 R117 = res1: as R84 on sheet IDD_measurement
R67 = res1: Resistor,10R,0603,1%,YAGEO; Ordered by: Subcon; ECCN_US/EU: NA
R77 R89 R99 R104 = res1: Resistor,100K,0603,1%,YAGEO; Manuf_Part_1: RC0603FR-07100KL; Ordered by: Subcon; ECCN_US/EU: NA
R87 R88 = res1: Resistor,1.5K,0603,1%,YAGEO; Manuf_Part_1: RC0603FR-071K5L; Value: 1K5; Ordered by: Subcon; ECCN_US/EU: NA
SB14 SB20 SB21 = SB_ON: as SB1 on sheet Arduino_ Connectors
SB15 SB22 = SB_OFF: Solder: NO
T11 T12 = MCD-01926: as T4 on sheet IDD_measurement
U15 = STLD40DPMR: Manuf_1: ST; Ordered by: STM; Ref St: 9176009; ECCN_US/EU: EAR99/NEC
Z1 = D Schottky: Schottky Diode; Code - JEDEC: DO-214-AA; Ordered by: STM; Ref St: 9151085; ECCN_US/EU: EAR99/NEC
ZZ1 = MCD-03367: LCD Module, TFT, 1.54-inch, 240(RGB)x240, CTP; Part_Type: Display; Part_Preference: Recommended; Manufacturer: SHENZEN FRIDA LCD; Component_Country_Of_Origin: China; ShowFields: YES; ID: 5483

## Sheet MCU.SchDoc: MCU
size A3; Author: P.A.; CompanyName: STMicroelectronics; Organization: Microcontrollers Division; Address1: 12, Rue Jules HOROWITZ; Address2: 38019 Grenoble; Address3: FRANCE; DocumentNumber: MB1261; Revision: B.01; SheetNumber: 11; SheetTotal: 15; Project: STM32L496G-DISCO
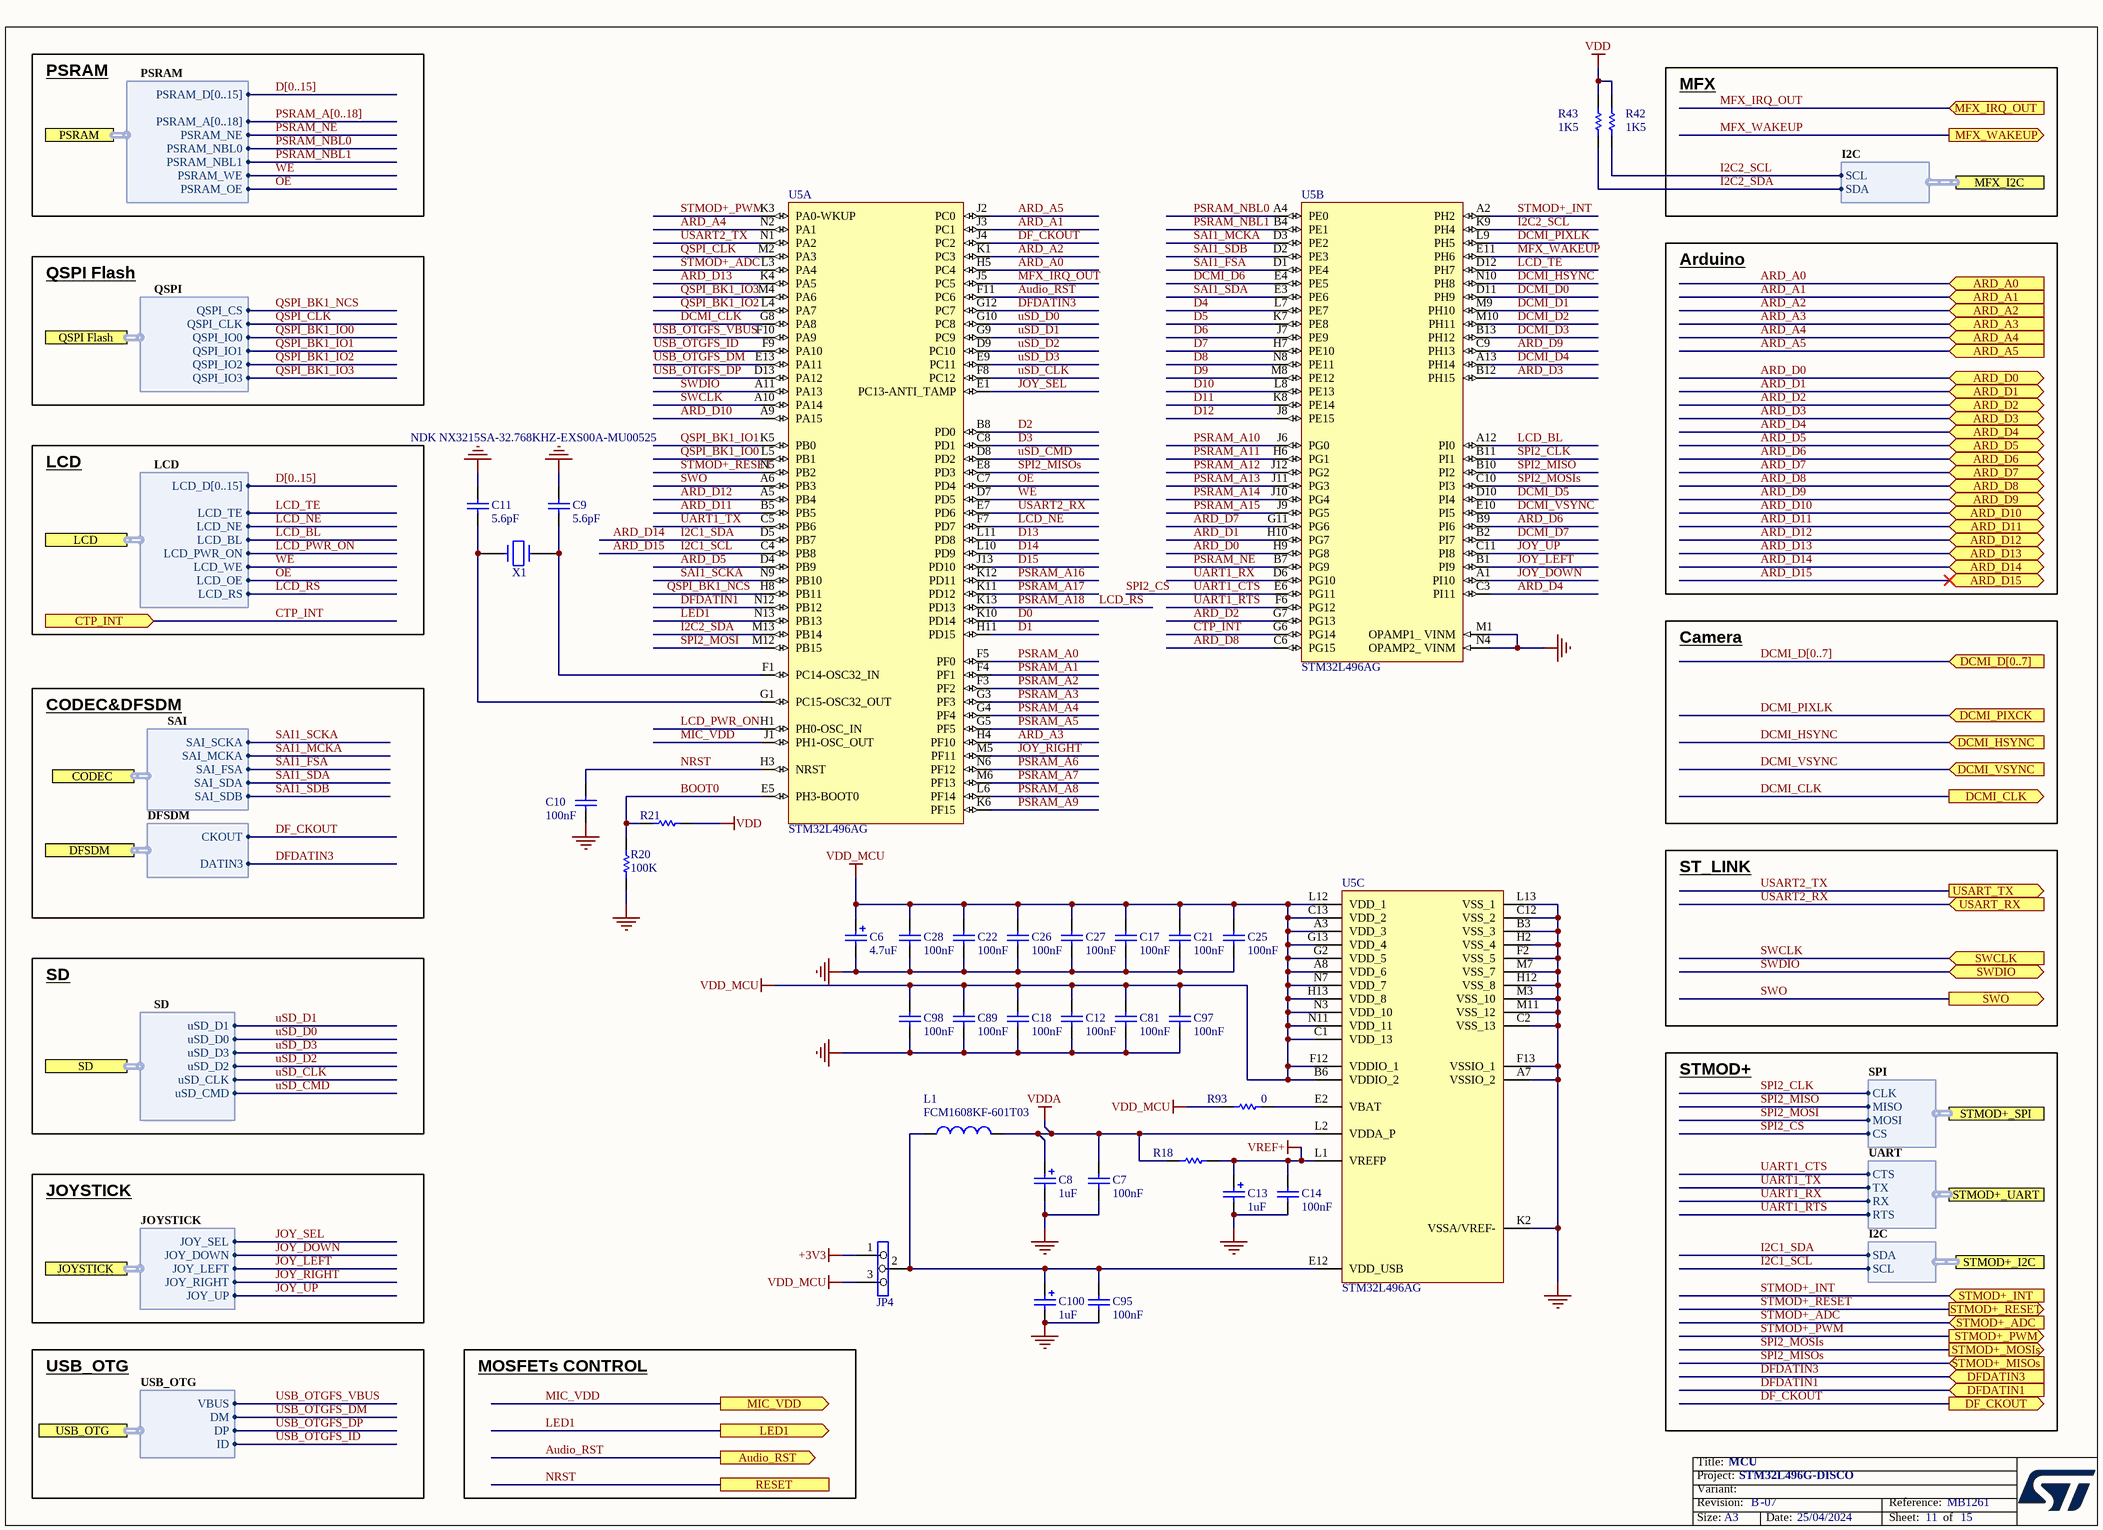
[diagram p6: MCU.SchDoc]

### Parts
C6  value 4.7uF  [TAN-A]  (hidden comment: TAJA475K016R)
C7  value 100nF  [0603C]  (hidden comment: CC0603KRX7R7BB104)
C8  value 1uF  [TAN-A]  (hidden comment: TAJA105K016R)
C9  5.6pF  [0603C]
C10  value 100nF  [0603C]  (hidden comment: CC0603KRX7R7BB104)
C11  5.6pF  [0603C]
C12  value 100nF  [0603C]  (hidden comment: CC0603KRX7R7BB104)
C13  value 1uF  [TAN-A]  (hidden comment: TAJA105K016R)
C14  value 100nF  [0603C]  (hidden comment: CC0603KRX7R7BB104)
C17  value 100nF  [0603C]  (hidden comment: CC0603KRX7R7BB104)
C18  value 100nF  [0603C]  (hidden comment: CC0603KRX7R7BB104)
C21  value 100nF  [0603C]  (hidden comment: CC0603KRX7R7BB104)
C22  value 100nF  [0603C]  (hidden comment: CC0603KRX7R7BB104)
C25  value 100nF  [0603C]  (hidden comment: CC0603KRX7R7BB104)
C26  value 100nF  [0603C]  (hidden comment: CC0603KRX7R7BB104)
C27  value 100nF  [0603C]  (hidden comment: CC0603KRX7R7BB104)
C28  value 100nF  [0603C]  (hidden comment: CC0603KRX7R7BB104)
C81  value 100nF  [0603C]  (hidden comment: CC0603KRX7R7BB104)
C89  value 100nF  [0603C]  (hidden comment: CC0603KRX7R7BB104)
C95  value 100nF  [0603C]  (hidden comment: CC0603KRX7R7BB104)
C97  value 100nF  [0603C]  (hidden comment: CC0603KRX7R7BB104)
C98  value 100nF  [0603C]  (hidden comment: CC0603KRX7R7BB104)
C100  value 1uF  [TAN-A]  (hidden comment: TAJA105K016R)
JP4  Jumper3  [SIP3]  (value not drawn)
L1  FCM1608KF-601T03  [L0603]
R18  (no value)  [0603R]
R20  value 100K  [0603R]  (hidden comment: RC0603FR-07100KL)
R21  (no value)  [0603R]
R42  value 1K5  [0603R]  (hidden comment: RC0603FR-071K5L)
R43  value 1K5  [0603R]  (hidden comment: RC0603FR-071K5L)
R93  value 0  [0603R]  (hidden comment: RC0603JR-070RL)
U5  STM32L496AG  [FBGA169_0R5_7X7]  (parts A,B,C of 3)
X1  NDK NX3215SA-32.768KHZ-EXS00A-MU00525  [XTAL_2SM_3R2X1R5]

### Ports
ARD_A0 (in), ARD_A1 (in), ARD_A2 (in), ARD_A3 (in), ARD_A4 (in), ARD_A5 (in), ARD_D0 (bidir), ARD_D1 (bidir), ARD_D2 (bidir), ARD_D3 (bidir), ARD_D4 (bidir), ARD_D5 (bidir), ARD_D6 (bidir), ARD_D7 (bidir), ARD_D8 (bidir), ARD_D9 (bidir), ARD_D10 (bidir), ARD_D11 (bidir), ARD_D12 (bidir), ARD_D13 (bidir), ARD_D14 (bidir), ARD_D15 (bidir), Audio_RST (out), CODEC (harness SAI), CTP_INT (in), DCMI_CLK (out), DCMI_D[0..7] (in), DCMI_HSYNC (in), DCMI_PIXCK (in), DCMI_VSYNC (in), DF_CKOUT (out), DFDATIN1 (in), DFDATIN3 (in), DFSDM (harness DFSDM), JOYSTICK (harness JOYSTICK), LCD (harness LCD), LED1 (out), MFX_I2C (harness I2C), MFX_IRQ_OUT (in), MFX_WAKEUP (out), MIC_VDD (out), PSRAM (harness PSRAM), QSPI Flash (harness QSPI), RESET, SD (harness SD), STMOD+_ADC (in), STMOD+_I2C (harness I2C), STMOD+_INT (in), STMOD+_MISOs (in), STMOD+_MOSIs (out), STMOD+_PWM (out), STMOD+_RESET (out), STMOD+_SPI (harness SPI), STMOD+_UART (harness UART), SWCLK (in), SWDIO (bidir), SWO (out), USART_RX (in), USART_TX (out), USB_OTG (harness USB_OTG)

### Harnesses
QSPI: QSPI_IO1, QSPI_IO0, QSPI_CLK, QSPI_CS, QSPI_IO2, QSPI_IO3
PSRAM: PSRAM_A[0..18], PSRAM_NE, PSRAM_NBL0, PSRAM_WE, PSRAM_OE, PSRAM_D[0..15], PSRAM_NBL1
LCD: LCD_NE, LCD_BL, LCD_WE, LCD_OE, LCD_D[0..15], LCD_RS, LCD_PWR_ON, LCD_TE
SAI: SAI_SDB, SAI_FSA, SAI_MCKA, SAI_SDA, SAI_SCKA
DFSDM: DATIN3, CKOUT
SD: uSD_D0, uSD_CLK, uSD_D1, uSD_D2, uSD_D3, uSD_CMD
JOYSTICK: JOY_SEL, JOY_DOWN, JOY_LEFT, JOY_RIGHT, JOY_UP
USB_OTG: VBUS, DM, DP, ID
I2C: SDA, SCL
SPI: MISO, MOSI, CLK, CS
UART: RX, TX, RTS, CTS

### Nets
+3V3: JP4.1  [project net 3V3_OUT]
GND: C6.2 C7.2 C8.2 C9.1 C10.2 C11.1 C12.2 C13.2 C14.2 C17.2 C18.2 C21.2 C22.2 C25.2 C26.2 C27.2 C28.2 C81.2 C89.2 C95.2 C97.2 C98.2 C100.2 R20.1 U5.A7(VSSIO_2) U5.B3(VSS_3) U5.C2(VSS_13) U5.C12(VSS_2) U5.F2(VSS_5) U5.F13(VSSIO_1) U5.H2(VSS_4) U5.H12(VSS_8) U5.K2(VSSA/VREF-) U5.L13(VSS_1) U5.M1(OPAMP1__VINM) U5.M3(VSS_10) U5.M7(VSS_7) U5.M11(VSS_12) U5.N4(OPAMP2__VINM)
VDD: R21.1 R42.1 R43.1
VDD_MCU: C6.1 C12.1 C17.1 C18.1 C21.1 C22.1 C25.1 C26.1 C27.1 C28.1 C81.1 C89.1 C97.1 C98.1 JP4.3 R93.2 U5.A3(VDD_3) U5.A8(VDD_6) U5.B6(VDDIO_2) U5.C1(VDD_13) U5.C13(VDD_2) U5.F12(VDDIO_1) U5.G2(VDD_5) U5.G13(VDD_4) U5.H13(VDD_8) U5.L12(VDD_1) U5.N3(VDD_10) U5.N7(VDD_7) U5.N11(VDD_11)
VDDA: C7.1 C8.1 L1.2 R18.2 U5.L2(VDDA_P)
VREF+: C13.1 C14.1 R18.1 U5.L1(VREFP)
ARD_A0: U5.H5(PC4) ; port ARD_A0
ARD_A1: U5.J3(PC1) ; port ARD_A1
ARD_A2: U5.K1(PC3) ; port ARD_A2
ARD_A3: U5.H4(PF10) ; port ARD_A3
ARD_A4: U5.N2(PA1) ; port ARD_A4
ARD_A5: U5.J2(PC0) ; port ARD_A5
ARD_D0: U5.H9(PG8) ; port ARD_D0
ARD_D1: U5.H10(PG7) ; port ARD_D1
ARD_D2: U5.G7(PG13) ; port ARD_D2
ARD_D3: U5.B12(PH15) ; port ARD_D3
ARD_D4: U5.C3(PI11) ; port ARD_D4
ARD_D5: U5.D4(PB9) ; port ARD_D5
ARD_D6: U5.B9(PI6) ; port ARD_D6
ARD_D7: U5.G11(PG6) ; port ARD_D7
ARD_D8: U5.C6(PG15) ; port ARD_D8
ARD_D9: U5.C9(PH13) ; port ARD_D9
ARD_D10: U5.A9(PA15) ; port ARD_D10
ARD_D11: U5.B5(PB5) ; port ARD_D11
ARD_D12: U5.A5(PB4) ; port ARD_D12
ARD_D13: U5.K4(PA5) ; port ARD_D13
ARD_D14: U5.D5(PB7) ; port ARD_D14, port STMOD+_I2C.SDA  [also labelled I2C1_SDA]
ARD_D15: U5.C4(PB8) ; port ARD_D15, port STMOD+_I2C.SCL  [also labelled I2C1_SCL]
Audio_RST: U5.F11(PC6) ; port Audio_RST
BOOT0: R20.2 R21.2 U5.E5(PH3-BOOT0)
CTP_INT: U5.G6(PG14) ; port CTP_INT
D0: U5.K10(PD14)
D1: U5.H11(PD15)
D2: U5.B8(PD0)
D3: U5.C8(PD1)
D4: U5.L7(PE7)
D5: U5.K7(PE8)
D6: U5.J7(PE9)
D7: U5.H7(PE10)
D8: U5.N8(PE11)
D9: U5.M8(PE12)
D10: U5.L8(PE13)
D11: U5.K8(PE14)
D12: U5.J8(PE15)
D13: U5.L11(PD8)
D14: U5.L10(PD9)
D15: U5.J13(PD10)
DCMI_CLK: U5.G8(PA8) ; port DCMI_CLK
DCMI_D0: U5.D11(PH9)
DCMI_D1: U5.M9(PH10)
DCMI_D2: U5.M10(PH11)
DCMI_D3: U5.B13(PH12)
DCMI_D4: U5.A13(PH14)
DCMI_D5: U5.D10(PI4)
DCMI_D6: U5.E4(PE5)
DCMI_D7: U5.B2(PI7)
DCMI_HSYNC: U5.N10(PH8) ; port DCMI_HSYNC
DCMI_PIXLK: U5.L9(PH5) ; port DCMI_PIXCK  [project net DCMI_PIXCK]
DCMI_VSYNC: U5.E10(PI5) ; port DCMI_VSYNC
DF_CKOUT: U5.J4(PC2) ; port DF_CKOUT, port DFSDM.CKOUT  [project net CKOUT]
DFDATIN1: U5.N12(PB12) ; port DFDATIN1
DFDATIN3: U5.G12(PC7) ; port DFDATIN3, port DFSDM.DATIN3  [project net DATIN3]
I2C2_SCL: R42.2 U5.K9(PH4) ; port MFX_I2C.SCL
I2C2_SDA: R43.2 U5.M13(PB14) ; port MFX_I2C.SDA
JOY_DOWN: U5.A1(PI10) ; port JOYSTICK.JOY_DOWN
JOY_LEFT: U5.B1(PI9) ; port JOYSTICK.JOY_LEFT
JOY_RIGHT: U5.M5(PF11) ; port JOYSTICK.JOY_RIGHT
JOY_SEL: U5.E1(PC13-ANTI_TAMP) ; port JOYSTICK.JOY_SEL
JOY_UP: U5.C11(PI8) ; port JOYSTICK.JOY_UP
LCD_BL: U5.A12(PI0) ; port LCD.LCD_BL
LCD_NE: U5.F7(PD7) ; port LCD.LCD_NE
LCD_PWR_ON: U5.H1(PH0-OSC_IN) ; port LCD.LCD_PWR_ON
LCD_RS: U5.K13(PD13) ; port LCD.LCD_RS  [also labelled PSRAM_A18]
LCD_TE: U5.D12(PH7) ; port LCD.LCD_TE
LED1: U5.N13(PB13) ; port LED1
MFX_IRQ_OUT: U5.J5(PC5) ; port MFX_IRQ_OUT
MFX_WAKEUP: U5.E11(PH6) ; port MFX_WAKEUP
MIC_VDD: U5.J1(PH1-OSC_OUT) ; port MIC_VDD
NRST: C10.1 U5.H3(NRST) ; port RESET
OE: U5.C7(PD4) ; port PSRAM.PSRAM_OE, port LCD.LCD_OE  [project net LCD_OE]
PSRAM_A0: U5.F5(PF0)
PSRAM_A1: U5.F4(PF1)
PSRAM_A2: U5.F3(PF2)
PSRAM_A3: U5.G3(PF3)
PSRAM_A4: U5.G4(PF4)
PSRAM_A5: U5.G5(PF5)
PSRAM_A6: U5.N6(PF12)
PSRAM_A7: U5.M6(PF13)
PSRAM_A8: U5.L6(PF14)
PSRAM_A9: U5.K6(PF15)
PSRAM_A10: U5.J6(PG0)
PSRAM_A11: U5.H6(PG1)
PSRAM_A12: U5.J12(PG2)
PSRAM_A13: U5.J11(PG3)
PSRAM_A14: U5.J10(PG4)
PSRAM_A15: U5.J9(PG5)
PSRAM_A16: U5.K12(PD11)
PSRAM_A17: U5.K11(PD12)
PSRAM_NBL0: U5.A4(PE0) ; port PSRAM.PSRAM_NBL0
PSRAM_NBL1: U5.B4(PE1) ; port PSRAM.PSRAM_NBL1
PSRAM_NE: U5.B7(PG9) ; port PSRAM.PSRAM_NE
QSPI_BK1_IO0: U5.L5(PB1) ; port QSPI Flash.QSPI_IO0
QSPI_BK1_IO1: U5.K5(PB0) ; port QSPI Flash.QSPI_IO1
QSPI_BK1_IO2: U5.L4(PA7) ; port QSPI Flash.QSPI_IO2
QSPI_BK1_IO3: U5.M4(PA6) ; port QSPI Flash.QSPI_IO3
QSPI_BK1_NCS: U5.H8(PB11) ; port QSPI Flash.QSPI_CS
QSPI_CLK: U5.M2(PA3) ; port QSPI Flash.QSPI_CLK
SAI1_FSA: U5.D1(PE4) ; port CODEC.SAI_FSA
SAI1_MCKA: U5.D3(PE2) ; port CODEC.SAI_MCKA
SAI1_SCKA: U5.N9(PB10) ; port CODEC.SAI_SCKA
SAI1_SDA: U5.E3(PE6) ; port CODEC.SAI_SDA
SAI1_SDB: U5.D2(PE3) ; port CODEC.SAI_SDB
SPI2_CLK: U5.B11(PI1) ; port STMOD+_SPI.CLK
SPI2_CS: U5.E6(PG11) ; port STMOD+_SPI.CS, port STMOD+_UART.CTS  [also labelled UART1_CTS]  [project net PMOD#1]
SPI2_MISO: U5.B10(PI2) ; port STMOD+_SPI.MISO
SPI2_MISOs: U5.E8(PD3) ; port STMOD+_MISOs
SPI2_MOSI: U5.M12(PB15) ; port STMOD+_SPI.MOSI
SPI2_MOSIs: U5.C10(PI3) ; port STMOD+_MOSIs
STMOD+_ADC: U5.L3(PA4) ; port STMOD+_ADC
STMOD+_INT: U5.A2(PH2) ; port STMOD+_INT  [project net PMOD#11]
STMOD+_PWM: U5.K3(PA0-WKUP) ; port STMOD+_PWM
STMOD+_RESET: U5.N5(PB2) ; port STMOD+_RESET  [project net PMOD#12]
SWCLK: U5.A10(PA14) ; port SWCLK
SWDIO: U5.A11(PA13) ; port SWDIO
SWO: U5.A6(PB3) ; port SWO
UART1_RTS: U5.F6(PG12) ; port STMOD+_UART.RTS
UART1_RX: U5.D6(PG10) ; port STMOD+_UART.RX
UART1_TX: U5.C5(PB6) ; port STMOD+_UART.TX
USART2_RX: U5.E7(PD6) ; port USART_RX
USART2_TX: U5.N1(PA2) ; port USART_TX
USB_OTGFS_DM: U5.E13(PA11) ; port USB_OTG.DM  [project net D_N]
USB_OTGFS_DP: U5.D13(PA12) ; port USB_OTG.DP  [project net D_P]
USB_OTGFS_ID: U5.F9(PA10) ; port USB_OTG.ID
USB_OTGFS_VBUS: U5.F10(PA9) ; port USB_OTG.VBUS
uSD_CLK: U5.F8(PC12) ; port SD.uSD_CLK
uSD_CMD: U5.D8(PD2) ; port SD.uSD_CMD
uSD_D0: U5.G10(PC8) ; port SD.uSD_D0
uSD_D1: U5.G9(PC9) ; port SD.uSD_D1
uSD_D2: U5.D9(PC10) ; port SD.uSD_D2
uSD_D3: U5.E9(PC11) ; port SD.uSD_D3
WE: U5.D7(PD5) ; port PSRAM.PSRAM_WE, port LCD.LCD_WE  [project net LCD_WE]
NetC9_2: C9.2 U5.F1(PC14-OSC32_IN) X1.1
NetC11_2: C11.2 U5.G1(PC15-OSC32_OUT) X1.2
NetC95_1: C95.1 C100.1 JP4.2 L1.1 U5.E12(VDD_USB)
NetR93_1: R93.1 U5.E2(VBAT)

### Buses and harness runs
bus D[0..15]
bus DCMI_D[0..7] = port DCMI_D[0..7]
bus PSRAM_A[0..18]

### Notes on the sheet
- PSRAM
- MFX
- Arduino
- QSPI Flash
- LCD
- Camera
- CODEC&DFSDM
- ST_LINK
- SD
- STMOD+
- JOYSTICK
- USB_OTG
- MOSFETs CONTROL

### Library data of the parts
C6 = Cap Pol1: TAN Capacitor,4.7uF,10%,16V,A Type,AVX; Ordered by: Subcon; ECCN_US/EU: NA
C7 C10 C12 C14 C17 C18 C21 C22 C25-C28 C81 C89 C95 C97 C98 = Cap: as C60 on sheet Camera
C8 C13 C100 = Cap Pol1: as C91 on sheet IDD_measurement
C9 C11 = Cap: Capacitor,5.6pF,0.25P,50V,NPO,0603; Manuf_1: YAGEO; Ordered by: Subcon
JP4 = Jumper3: Manuf_1: lyconn; Manuf_Part_1: 313103S111116; Ordered by: Subcon; ECCN_US/EU: NA
L1 = MCD-00047: as L8 on sheet IDD_measurement
R18 = res1: Resistor, 0 ,0603,1%,YAGEO; Manuf_Part_1: RC0603JR-070RL; Value: 0; Ordered by: Subcon; ECCN_US/EU: NA
R20 = res1: as R84 on sheet IDD_measurement
R21 = res1: as R77 on sheet LCD
R42 R43 = res1: Resistor,1.5K,0603,1%,YAGEO; Ordered by: Subcon; ECCN_US/EU: NA
R93 = res1: as R105 on sheet IDD_measurement
U5 = STM32L496G: Ordered by: STM; Ref St: TBD; ECCN_US/EU: 3A991A2/NEC
X1 = CRYSTAL_32K: 32.768kHz Crystal; Ordered by: STM; ECCN_US/EU: EAR99/NEC; Ref St: 9157034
